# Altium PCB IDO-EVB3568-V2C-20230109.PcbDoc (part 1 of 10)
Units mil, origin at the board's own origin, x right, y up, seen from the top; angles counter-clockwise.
Board outline 5318 x 3544 mil, 2 copper layers (TOP, BOTTOM), stack 6.8 mil thick; 790 components, 626 nets, 2890 pads, 1922 vias.
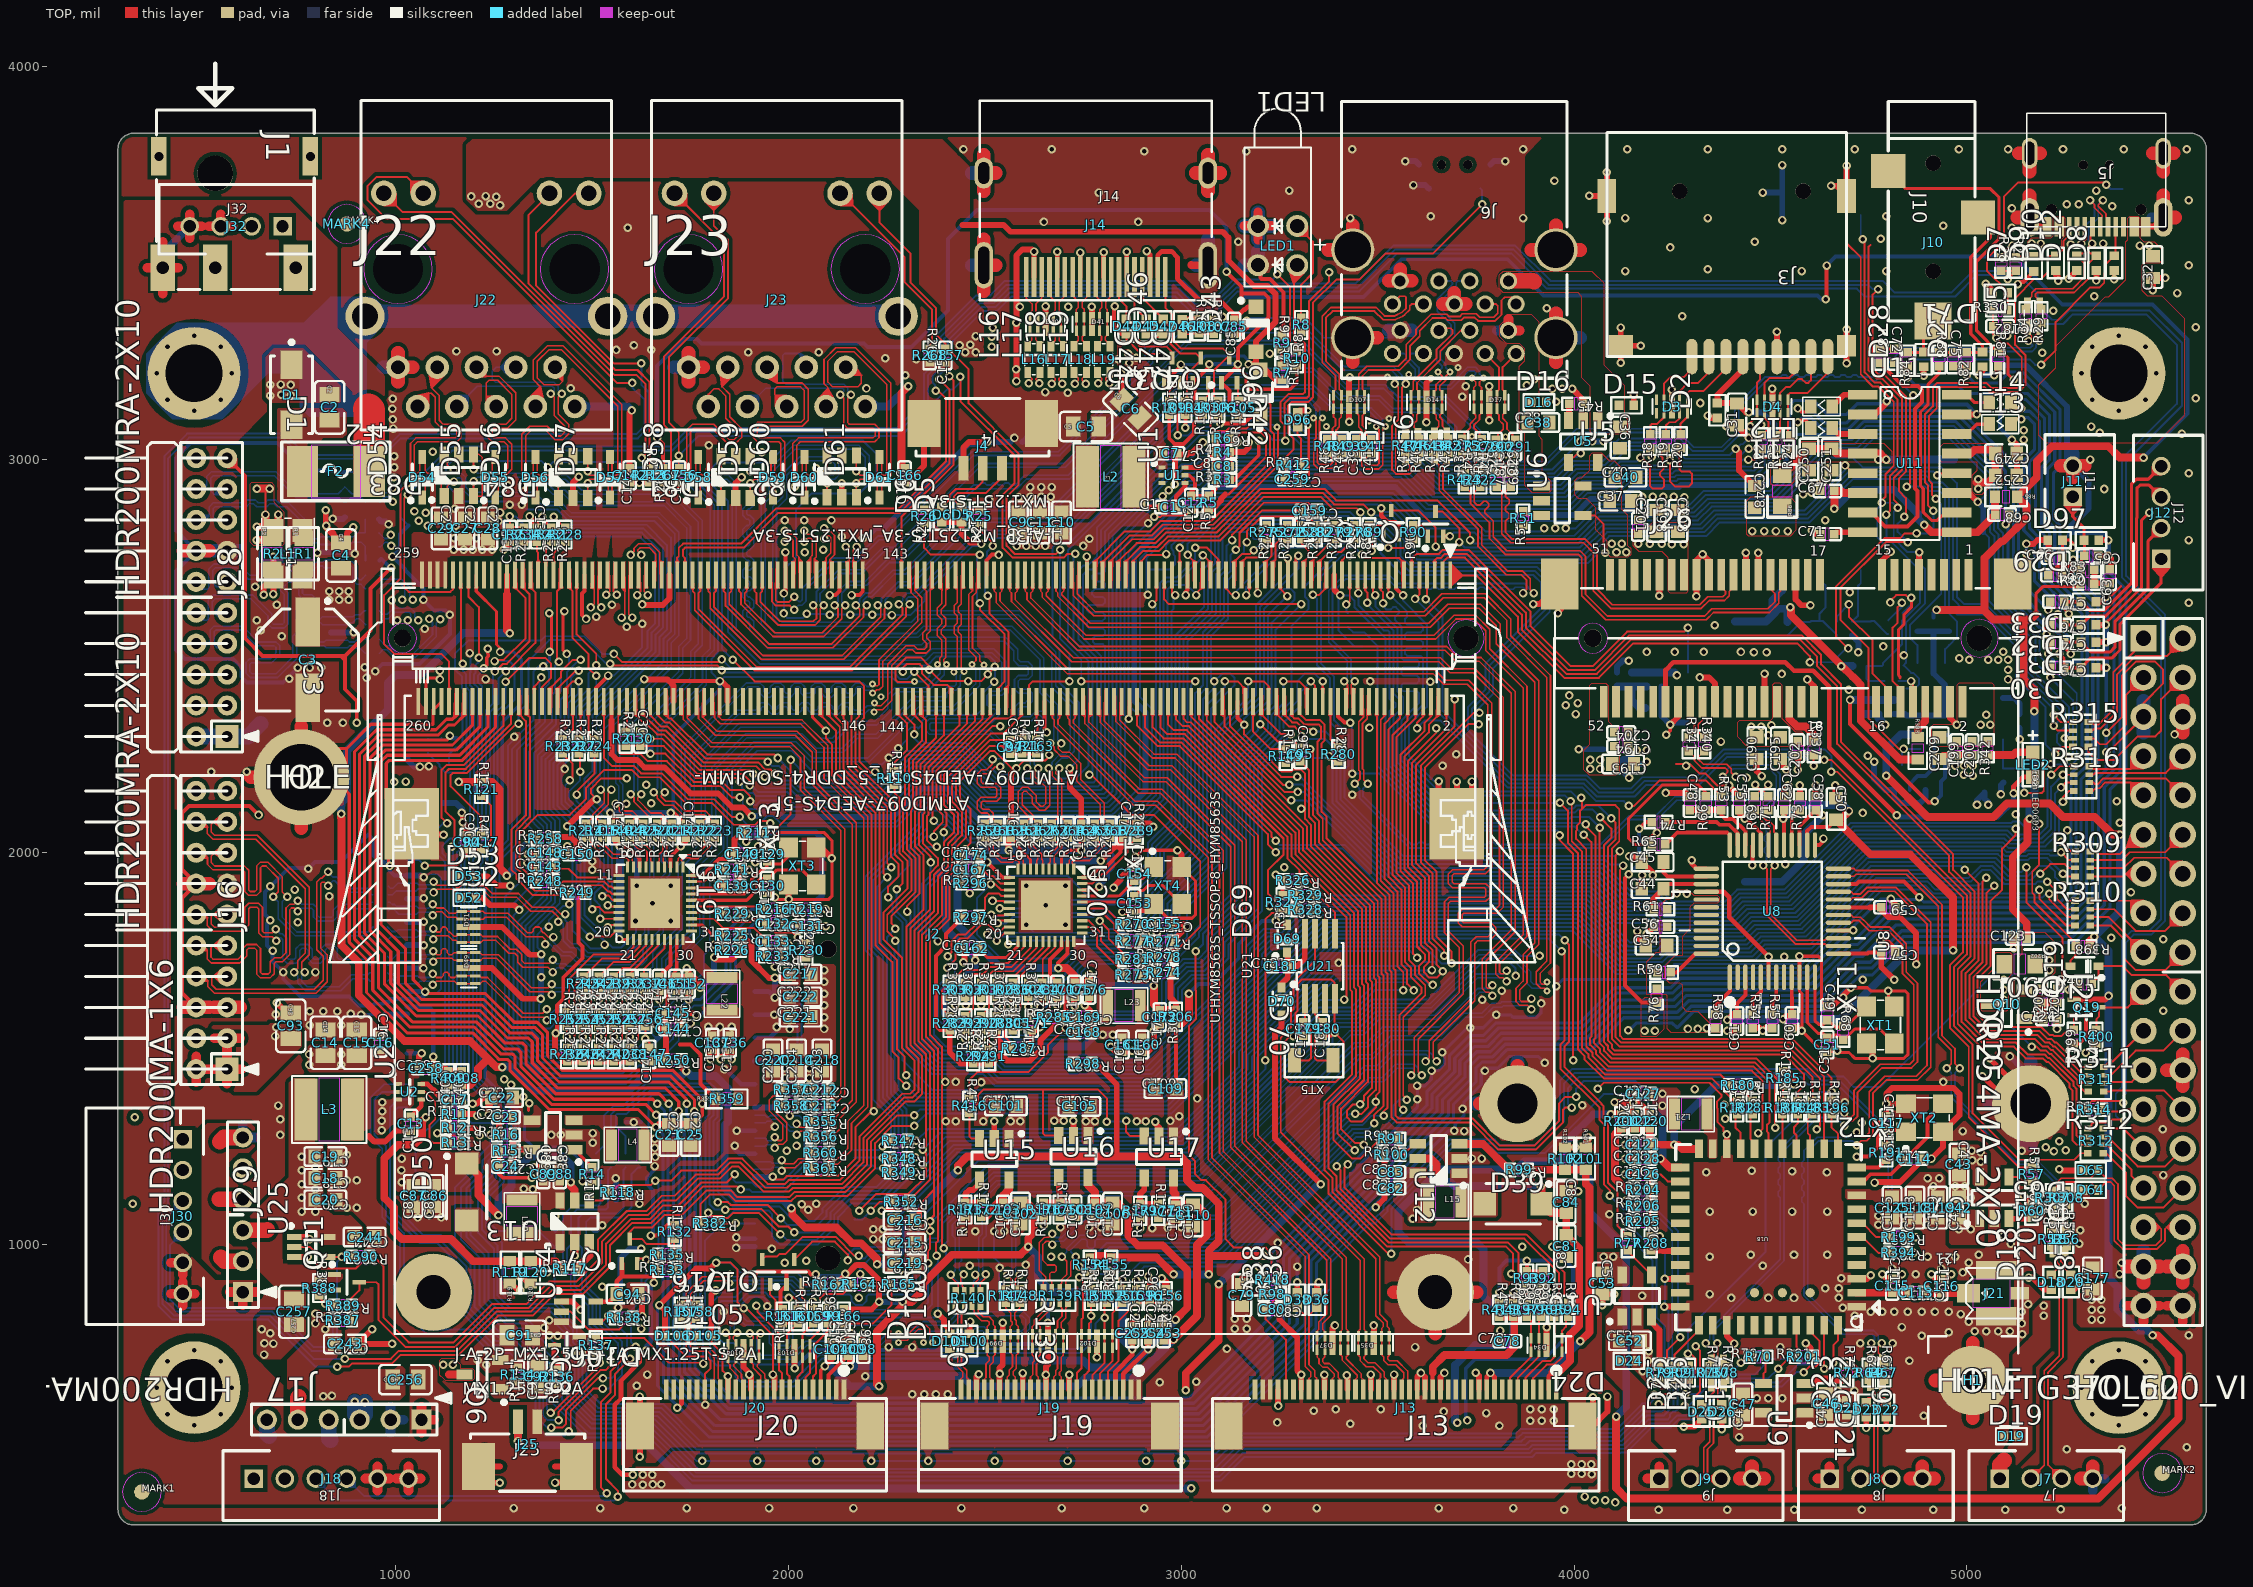
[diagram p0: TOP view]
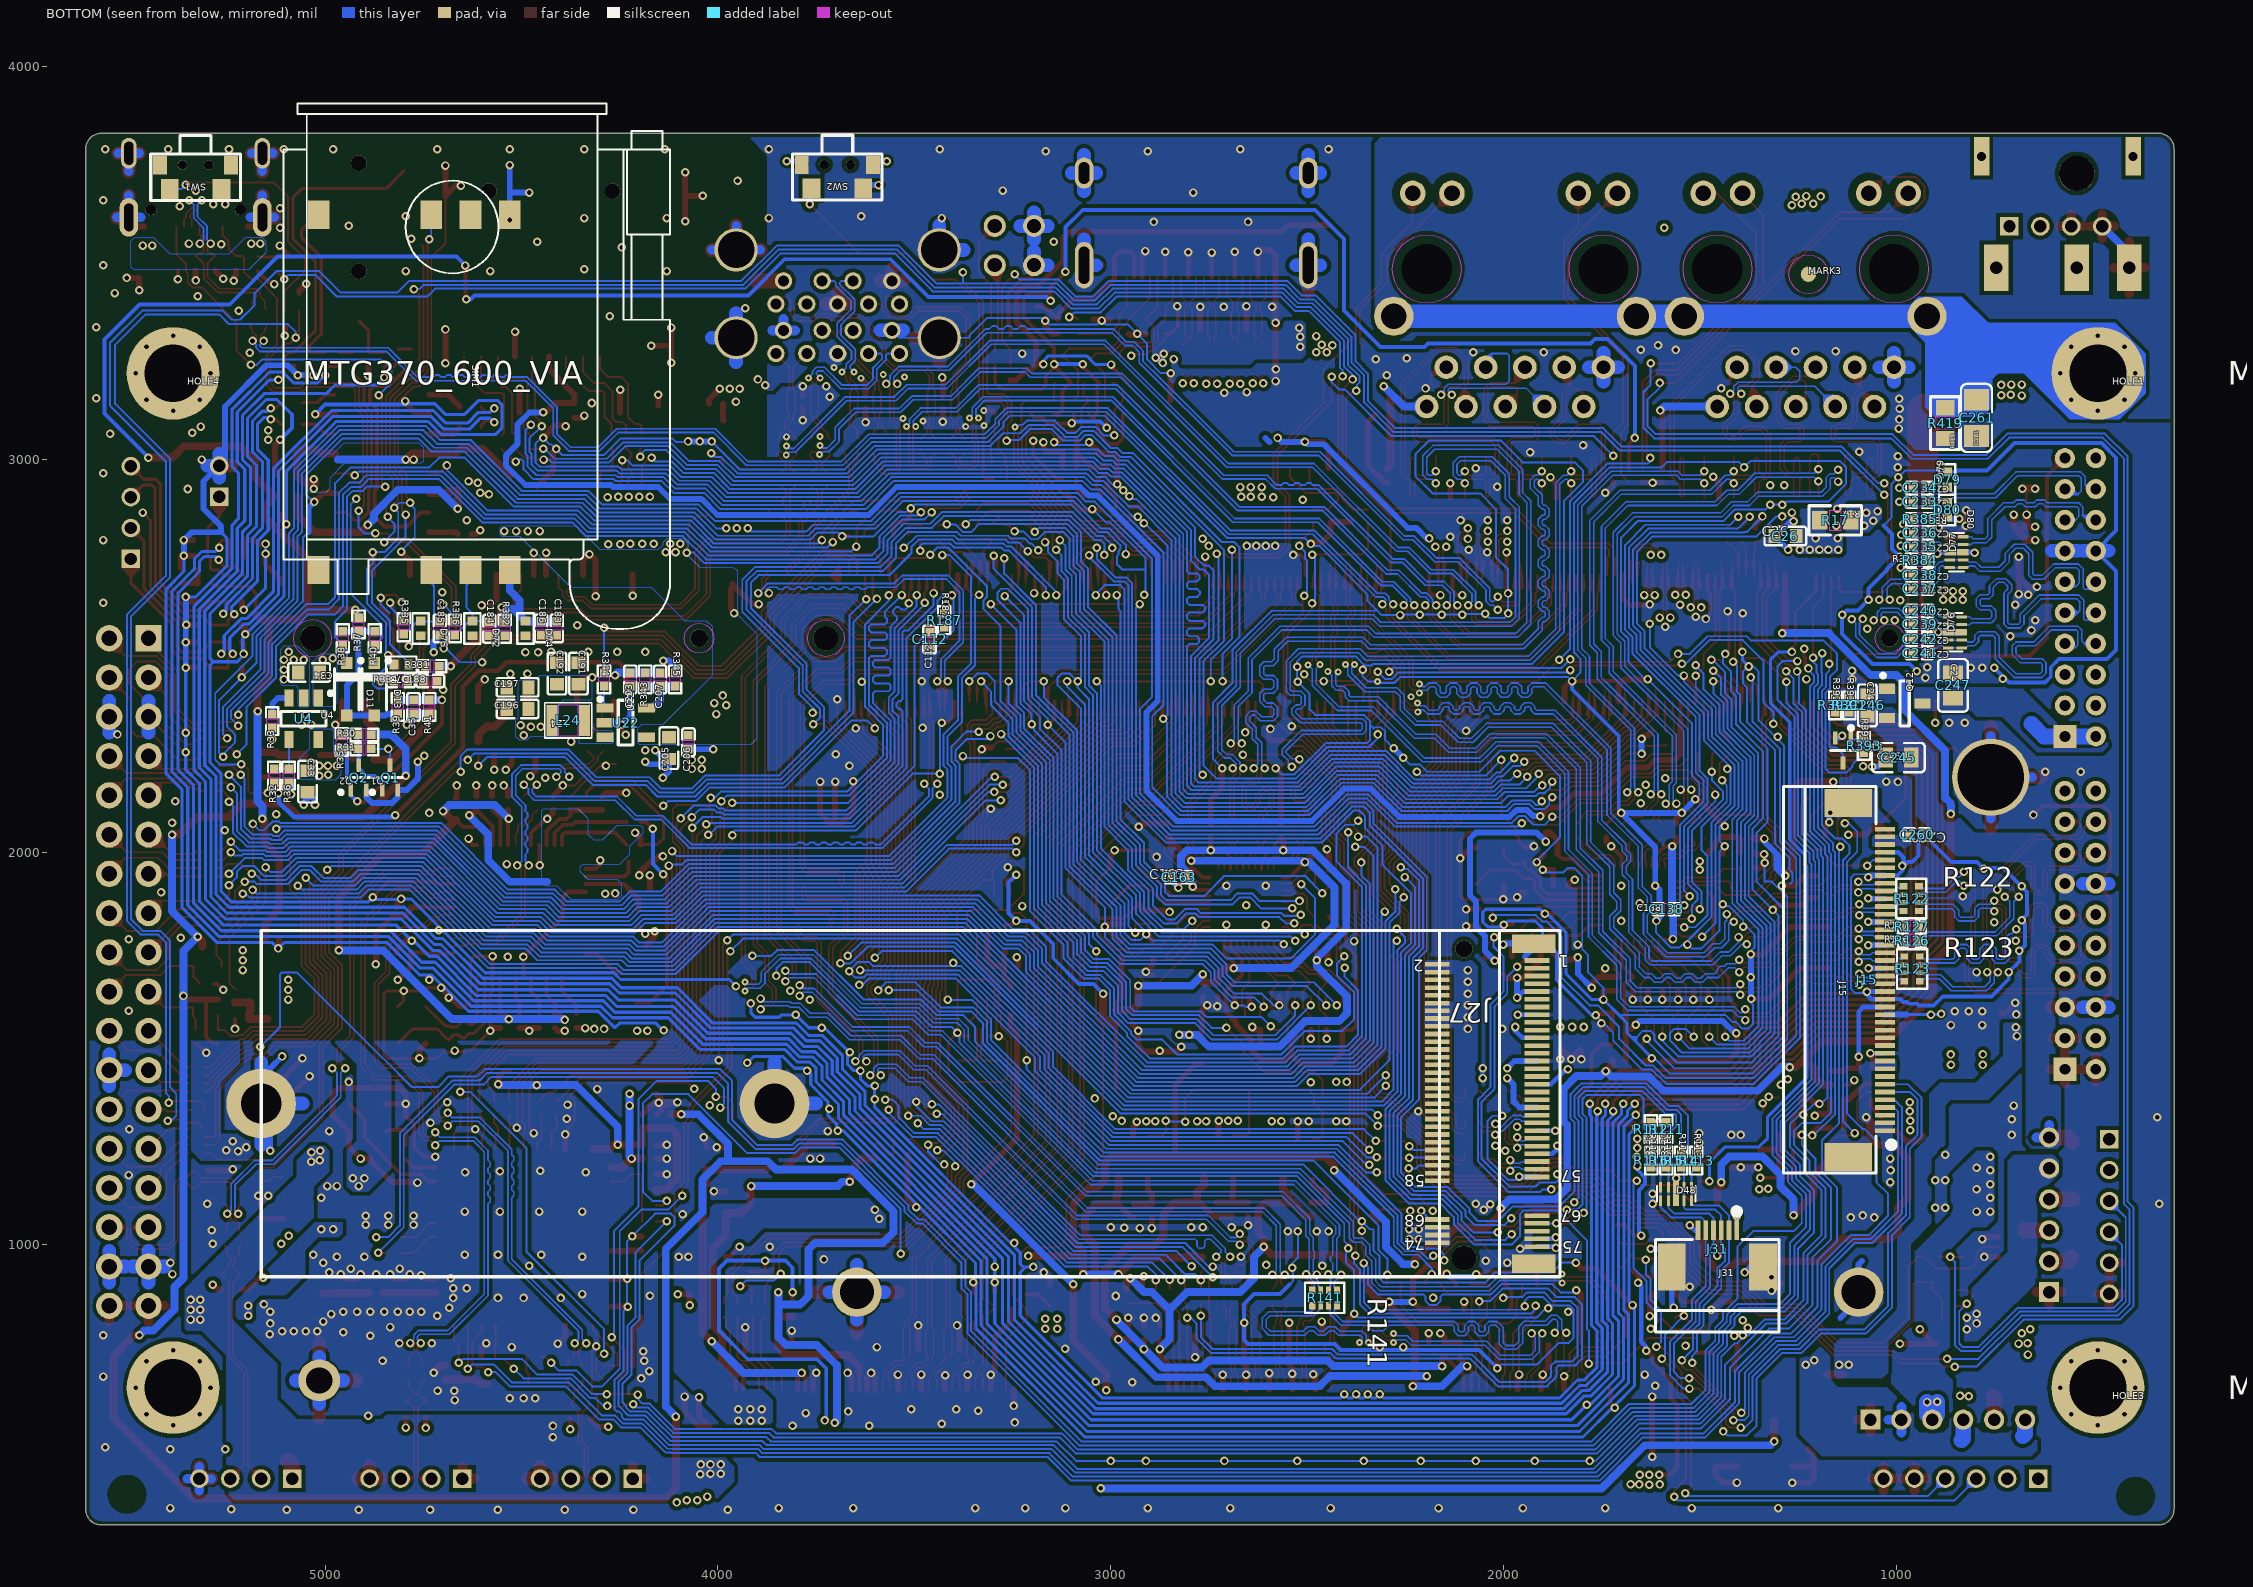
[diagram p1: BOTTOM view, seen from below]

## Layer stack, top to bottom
Top Solder: solder mask 0.4, Solder Resist, Dk 3.5
TOP: signal copper 1.65
Dielectric 1: core 3.5, FR-4, Dk 4.5
BOTTOM: signal copper 1.65
Bottom Solder: solder mask 0.4, Solder Resist, Dk 3.5

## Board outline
4436,3831 5570,3831 cw(c5570,3791) 5610,327 cw(c5570,327) 332,287 cw(c332,327) 292,3791 cw(c332,3791) 4309,3831

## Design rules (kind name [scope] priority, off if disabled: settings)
Clearance [All] p1: gap=10 ignorepadtopadclearanceinfootprint=FALSE except(0: Arc-Hole Track-Hole SMDPad-Hole THPad-Hole Via-Hole Fill-Hole Poly-Hole Region-Hole Text-Hole)
DiffPairsRouting [All] p1: maxlimit=10 minlimit=10 mostfreqgap=10 toplayer_minwidth=15 toplayer_maxwidth=15 toplayer_prefwidth=15 bottomlayer_minwidth=15 bottomlayer_maxwidth=15 bottomlayer_prefwidth=15 maxuncoupledlength=500
PlaneConnect [All] p1: planeconnectstyle=Direct reliefexpansion=20 reliefentries=4 reliefconductorwidth=10 reliefairgap=10
PolygonConnect [All] p1: connectstyle=Direct reliefconductorwidth=10 reliefentries=4 polygonreliefangle="90 Angle" airgapwidth=10
RoutingVias [All] p1: holewidth=28 width=50 viastyle="Through Hole" minholewidth=28 minwidth=50 maxholewidth=28 maxwidth=50
SolderMaskExpansion [All] p1: expansion=4 istentingtop=FALSE
Width [All] p1: maxlimit=10 minlimit=10 preferedwidth=10 impedanceprofiledriven=TRUE minimp=186.350000 maximp=187.750000 favimp=169.560000
28 further rules are at their usual default settings.

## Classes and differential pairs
differential pair DP2: +USB3_OTG0_SSTXN_ -USB3_OTG0_SSTXP_
differential pair DIFFPAIR52: +USB3_OTG0_SSTXN -USB3_OTG0_SSTXP
differential pair DP1: +USB3_OTG0_SSRXN_ -USB3_OTG0_SSRXP_
differential pair DIFFPAIR51: +USB3_OTG0_SSRXN -USB3_OTG0_SSRXP
differential pair DIFFPAIR91: +USB3_OTG0_DM_ -USB3_OTG0_DP_
differential pair DIFFPAIR50: +USB3_OTG0_DM -USB3_OTG0_DP
differential pair DIFFPAIR14: +USB3_HOST1_SSTXN_ -USB3_HOST1_SSTXP_
differential pair DIFFPAIR21: +USB3_HOST1_SSTXN -USB3_HOST1_SSTXP
differential pair DIFFPAIR15: +USB3_HOST1_SSRXN_ -USB3_HOST1_SSRXP_
differential pair DIFFPAIR20: +USB3_HOST1_SSRXN -USB3_HOST1_SSRXP
differential pair DIFFPAIR16: +USB3_HOST1_DM_ -USB3_HOST1_DP_
differential pair DIFFPAIR19: +USB3_HOST1_DM -USB3_HOST1_DP
differential pair DIFFPAIR49: +USB2_HOST3_DM -USB2_HOST3_DP
differential pair DIFFPAIR17: +USB2_HOST2_DM_ -USB2_HOST2_DP_
differential pair DIFFPAIR18: +USB2_HOST2_DM -USB2_HOST2_DP
differential pair DIFFPAIR79: +PHY1_MDI3- -PHY1_MDI3+
differential pair DIFFPAIR82: +PHY1_MDI2- -PHY1_MDI2+
differential pair DIFFPAIR80: +PHY1_MDI1- -PHY1_MDI1+
differential pair DIFFPAIR81: +PHY1_MDI0- -PHY1_MDI0+
differential pair DIFFPAIR83: +PHY0_MDI3- -PHY0_MDI3+
differential pair DIFFPAIR84: +PHY0_MDI2- -PHY0_MDI2+
differential pair DIFFPAIR85: +PHY0_MDI1- -PHY0_MDI1+
differential pair DIFFPAIR86: +PHY0_MDI0- -PHY0_MDI0+
differential pair DIFFPAIR60: +PCIE20_TXN_ -PCIE20_TXP_
differential pair DIFFPAIR37: +PCIE20_TXN -PCIE20_TXP
differential pair DIFFPAIR62: +PCIE20_TX_N -PCIE20_TX_P
differential pair DIFFPAIR59: +PCIE20_RXN_ -PCIE20_RXP_
differential pair DIFFPAIR36: +PCIE20_RXN -PCIE20_RXP
differential pair DIFFPAIR61: +PCIE20_REFCLKN_ -PCIE20_REFCLKP_
differential pair DIFFPAIR35: +PCIE20_REFCLKN -PCIE20_REFCLKP
differential pair DIFFPAIR22: +MIPI_DSI_TX1_D3N -MIPI_DSI_TX1_D3P
differential pair DIFFPAIR23: +MIPI_DSI_TX1_D2N -MIPI_DSI_TX1_D2P
differential pair DIFFPAIR25: +MIPI_DSI_TX1_D1N -MIPI_DSI_TX1_D1P
differential pair DIFFPAIR78: +MIPI_DSI_TX1_D0N -MIPI_DSI_TX1_D0P
differential pair DIFFPAIR24: +MIPI_DSI_TX1_CLKN -MIPI_DSI_TX1_CLKP
differential pair DIFFPAIR26: +MIPI_DSI_TX0_D3N -MIPI_DSI_TX0_D3P
differential pair DIFFPAIR27: +MIPI_DSI_TX0_D2N -MIPI_DSI_TX0_D2P
differential pair DIFFPAIR29: +MIPI_DSI_TX0_D1N -MIPI_DSI_TX0_D1P
differential pair DIFFPAIR64: +MIPI_DSI_TX0_D0N -MIPI_DSI_TX0_D0P
differential pair DIFFPAIR28: +MIPI_DSI_TX0_CLKN -MIPI_DSI_TX0_CLKP
differential pair DIFFPAIR45: +MIPI_CSI_RX_D3N -MIPI_CSI_RX_D3P
differential pair DIFFPAIR46: +MIPI_CSI_RX_D2N -MIPI_CSI_RX_D2P
differential pair DIFFPAIR47: +MIPI_CSI_RX_D1N -MIPI_CSI_RX_D1P
differential pair DIFFPAIR48: +MIPI_CSI_RX_D0N -MIPI_CSI_RX_D0P
differential pair DIFFPAIR43: +MIPI_CSI_RX_CLK1N -MIPI_CSI_RX_CLK1P
differential pair DIFFPAIR44: +MIPI_CSI_RX_CLK0N -MIPI_CSI_RX_CLK0P
differential pair DIFFPAIR53: +MIPI_CSI_D3N_ -MIPI_CSI_D3P_
differential pair DIFFPAIR77: +MIPI_CSI_D3N -MIPI_CSI_D3P
differential pair DIFFPAIR54: +MIPI_CSI_D2N_ -MIPI_CSI_D2P_
differential pair DIFFPAIR55: +MIPI_CSI_D2N -MIPI_CSI_D2P
differential pair DIFFPAIR57: +MIPI_CSI_D1N -MIPI_CSI_D1P
differential pair DIFFPAIR58: +MIPI_CSI_D0N -MIPI_CSI_D0P
differential pair DIFFPAIR87: +MIPI_CSI_CLK1N -MIPI_CSI_CLK1P
differential pair DIFFPAIR56: +MIPI_CSI_CLK0N -MIPI_CSI_CLK0P
differential pair DIFFPAIR68: +LVDS_TX0_D3N -LVDS_TX0_D3P
differential pair DIFFPAIR67: +LVDS_TX0_D2N -LVDS_TX0_D2P
differential pair DIFFPAIR65: +LVDS_TX0_D1N -LVDS_TX0_D1P
differential pair DIFFPAIR63: +LVDS_TX0_D0N -LVDS_TX0_D0P
differential pair DIFFPAIR66: +LVDS_TX0_CLKN -LVDS_TX0_CLKP
differential pair DIFFPAIR73: +LAN1_D- -LAN1_D+
differential pair DIFFPAIR74: +LAN1_C- -LAN1_C+
differential pair DIFFPAIR75: +LAN1_B- -LAN1_B+
differential pair DIFFPAIR76: +LAN1_A- -LAN1_A+
differential pair DIFFPAIR69: +LAN0_D- -LAN0_D+
differential pair DIFFPAIR70: +LAN0_C- -LAN0_C+
differential pair DIFFPAIR71: +LAN0_B- -LAN0_B+
differential pair DIFFPAIR72: +LAN0_A- -LAN0_A+
differential pair DIFFPAIR0: +HDMI_TX_D2N_ -HDMI_TX_D2P_
differential pair DIFFPAIR7: +HDMI_TX_D2N -HDMI_TX_D2P
differential pair DIFFPAIR1: +HDMI_TX_D1N_ -HDMI_TX_D1P_
differential pair DIFFPAIR6: +HDMI_TX_D1N -HDMI_TX_D1P
differential pair DIFFPAIR2: +HDMI_TX_D0N_ -HDMI_TX_D0P_
differential pair DIFFPAIR5: +HDMI_TX_D0N -HDMI_TX_D0P
differential pair DIFFPAIR3: +HDMI_TX_CLKN_ -HDMI_TX_CLKP_
differential pair DIFFPAIR4: +HDMI_TX_CLKN -HDMI_TX_CLKP
differential pair DIFFPAIR92: +FE1_1_DM4 -FE1_1_DP4
differential pair DIFFPAIR11: +FE1_1_DM3 -FE1_1_DP3
differential pair DIFFPAIR8: +FE1_1_DM2 -FE1_1_DP2
differential pair DIFFPAIR13: +FE1_1_DM1 -FE1_1_DP1
differential pair DIFFPAIR94: +FE1_1_DM0 -FE1_1_DP0
differential pair DIFFPAIR34: +EDP_TX_D3N_ -EDP_TX_D3P_
differential pair DIFFPAIR41: +EDP_TX_D3N -EDP_TX_D3P
differential pair DIFFPAIR32: +EDP_TX_D2N_ -EDP_TX_D2P_
differential pair DIFFPAIR40: +EDP_TX_D2N -EDP_TX_D2P
differential pair DIFFPAIR31: +EDP_TX_D1N_ -EDP_TX_D1P_
differential pair DIFFPAIR39: +EDP_TX_D1N -EDP_TX_D1P
differential pair DIFFPAIR30: +EDP_TX_D0N_ -EDP_TX_D0P_
differential pair DIFFPAIR38: +EDP_TX_D0N -EDP_TX_D0P
differential pair DIFFPAIR33: +EDP_TX_AUXN_ -EDP_TX_AUXP_
differential pair DIFFPAIR42: +EDP_TX_AUXN -EDP_TX_AUXP
differential pair DIFFPAIR93: +DM4 -DP4
differential pair DIFFPAIR10: +DM3_ -DP3_
differential pair DIFFPAIR9: +DM2_ -DP2_
differential pair DIFFPAIR12: +DM1_ -DP1_
differential pair DIFFPAIR88: +DM_1 -DP_1
differential pair DIFFPAIR89: +5G_SSTXN -5G_SSTXP
differential pair DIFFPAIR90: +5G_SSRXN -5G_SSRXP

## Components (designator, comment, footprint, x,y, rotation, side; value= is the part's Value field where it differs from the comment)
C1 "C-0402_C0402_100NF" SILKSCREEN_TOP#1 2969,2878.99 r0 top
C2 "C-0805_C0805_10UF" SILKSCREEN_TOP#2 831,3133 r270 top
C3 "C-AL-SMD_CAPAE660X770_100UF/25V" SILKSCREEN_TOP#3 775,2490 r270 top
C4 "C-0805_C0805_10UF" SILKSCREEN_TOP#2 860,2756 r270 top
C5 "C-0805_C0805_10UF" SILKSCREEN_TOP#2 2757,3084 r0 top
C6 "C-0805_C0805_10UF" SILKSCREEN_TOP#2 2870.72,3129.11 r315 top
C7 "C-0402_C0402_100NF" SILKSCREEN_TOP#1 2972,3016.01 r180 top
C8 "C-0402_C0402_100PF" SILKSCREEN_TOP#1 3105,2982.99 r0 top
C9 "C-0805_C0603_22UF" SILKSCREEN_TOP#4 2585,2840 r90 top
C10 "C-0805_C0603_22UF" SILKSCREEN_TOP#4 2695,2840 r90 top
C11 "C-0805_C0603_22UF" SILKSCREEN_TOP#4 2640,2840 r90 top
C12 "C-0402_C0402_100NF" SILKSCREEN_TOP#1 3025.01,2890 r90 top
C13 "C-0402_C0402_100NF" SILKSCREEN_TOP#1 1038.01,1309 r90 top
C14 "C-0805_C0805_10UF" SILKSCREEN_TOP#2 820,1515 r270 top
C15 "C-0805_C0805_10UF" SILKSCREEN_TOP#2 900,1515 r270 top
C16 "C-0402_C0402_100NF" SILKSCREEN_TOP#1 959.99,1515 r270 top
C17 "C-0402_C0402_100PF" SILKSCREEN_TOP#1 1150,1369.99 r0 top
C18 "C-0805_C0603_22UF" SILKSCREEN_TOP#4 820,1170 r180 top
C19 "C-0805_C0603_22UF" SILKSCREEN_TOP#4 820,1225 r180 top
C20 "C-0805_C0603_22UF" SILKSCREEN_TOP#4 820,1115 r180 top
C21 "C-0603_C0603_22UF" SILKSCREEN_TOP#4 1695,1280 r270 top
C22 "C-0603_C0603_10UF" SILKSCREEN_TOP#4 1270,1375 r0 top
C23 "C-0402_C0402_1UF" SILKSCREEN_TOP#1 1280,1324.99 r0 top
C24 "C-0402_C0402_47PF" SILKSCREEN_TOP#1 1280,1200.01 r180 top
C25 "C-0603_C0603_22UF" SILKSCREEN_TOP#4 1750,1280 r270 top
C26 "C-0805_C0603_22UF" SILKSCREEN_BOTTOM#1 1282,2805 r0 bottom
C27 "C-0805_C0603_22UF" SILKSCREEN_TOP#4 1176,2825 r270 top
C28 "C-0805_C0603_22UF" SILKSCREEN_TOP#4 1234,2825 r270 top
C29 "C-0805_C0603_22UF" SILKSCREEN_TOP#4 1115,2825 r270 top
C30 "C-0402_C0402_6.8PF" SILKSCREEN_TOP#1 1621.99,2289 r270 top
C31 "C-0603_C0603_10UF" ASSEMBLY_TOP#1 4415,3115 r90 top
C32 "C-0603_C0603_10UF" ASSEMBLY_TOP#1 5474,3490 r90 top
C33 "C-0603_C0603_10UF" ASSEMBLY_BOTTOM#1 5045,2180 r270 bottom
C34 "C-0603_C0603_10UF" ASSEMBLY_BOTTOM#1 5041,2458 r0 bottom
C35 "C-0402_C0402_1UF" ASSEMBLY_BOTTOM#2 4774.99,2370 r90 bottom
C36 "C-0603_C0603_10UF" ASSEMBLY_TOP#1 4117,3056 r270 top
C37 "C-0603_C0603_10UF" ASSEMBLY_TOP#1 4118,2894 r0 top
C38 "C-0603_C0603_10UF" SILKSCREEN_TOP#4 3909,3094 r0 top
C39 "C-0402_C0402_100NF" SILKSCREEN_TOP#1 3445.01,3034 r90 top
C40 "C-0603_C0603_10UF" SILKSCREEN_TOP#4 4131,2955 r0 top
C41 "C-0402_C0402_100NF" SILKSCREEN_TOP#1 3483.01,3034 r90 top
C42 "C-0603_C0603_10UF" SILKSCREEN_TOP#4 4980,1095 r90 top
C43 "C-0603_C0603_10UF" SILKSCREEN_TOP#4 4980,1205 r270 top
C44 "C-0603_C0603_10UF" ASSEMBLY_TOP#1 4200,1907 r0 top
C45 "C-0603_C0603_10UF" ASSEMBLY_TOP#1 4200,1975 r0 top
C46 "C-0603_C0603_10UF" SILKSCREEN_TOP#4 4642,595 r90 top
C47 "C-0603_C0603_10UF" SILKSCREEN_TOP#4 4430,594 r90 top
C48 "C-0402_C0402_NC/1UF" ASSEMBLY_TOP#2 4294.99,2125 r270 top
C49 "C-0402_C0402_18PF" ASSEMBLY_TOP#2 4644.99,1590 r270 top
C50 "C-0603_C0603_10UF" ASSEMBLY_TOP#1 4667,2110 r270 top
C51 "C-0402_C0402_18PF" SILKSCREEN_TOP#1 4645.01,1510 r90 top
C52 "C-0603_C0603_10UF" SILKSCREEN_TOP#4 4142,756 r0 top
C53 "C-0603_C0603_10UF" SILKSCREEN_TOP#4 4072,902 r270 top
C54 "C-0603_C0603_10UF" ASSEMBLY_TOP#1 4210,1763 r0 top
C55 "C-0402_C0402_100NF" ASSEMBLY_TOP#2 4419.99,2125 r270 top
C56 "C-0402_C0402_100NF" ASSEMBLY_TOP#2 4220,1809.99 r0 top
C57 "C-0402_C0402_100NF" ASSEMBLY_TOP#2 4800,1745.01 r180 top
C58 "C-0402_C0402_100NF" ASSEMBLY_TOP#2 4614.99,2125 r270 top
C59 "C-0402_C0402_100NF" ASSEMBLY_TOP#2 4800,1860.01 r180 top
C60 "C-0402_C0402_100NF" ASSEMBLY_TOP#2 4555.01,1570 r90 top
C61 "C-0402_C0402_100NF" ASSEMBLY_TOP#2 4415.01,1570 r90 top
C62 "C-0402_C0402_100NF" ASSEMBLY_TOP#2 4534.99,2125 r270 top
C63 "C-0402_C0402_1UF" ASSEMBLY_TOP#2 5364.01,2703 r90 top
C64 "C-0402_C0402_1UF" ASSEMBLY_TOP#2 5225,2705.01 r180 top
C65 "C-0402_C0402_220PF" ASSEMBLY_TOP#2 5317,2755.01 r180 top
C66 "C-0402_C0402_1UF" ASSEMBLY_TOP#2 5226,2749.99 r0 top
C67 "C-0402_C0402_100NF" ASSEMBLY_TOP#2 4645,2919.99 r0 top
C68 "C-0402_C0402_100NF" ASSEMBLY_TOP#2 5090,2860.01 r180 top
C71 "C-0402_C0402_1UF" ASSEMBLY_TOP#2 4645,2809.99 r0 top
C72 "C-0402_C0402_100NF" ASSEMBLY_TOP#2 4814.99,3264 r270 top
C73 "C-0402_C0402_1NF" ASSEMBLY_TOP#2 5230,2470.01 r180 top
C74 "C-0402_C0402_1NF" ASSEMBLY_TOP#2 5230,2535.01 r180 top
C75 "C-0402_C0402_100NF" ASSEMBLY_TOP#2 4964.99,3255 r270 top
C76 "C-0402_C0402_1NF" ASSEMBLY_TOP#2 5230,2579.01 r180 top
C77 "C-0402_C0402_1NF" ASSEMBLY_TOP#2 5230,2638.01 r180 top
C78 "C-0402_C0402_1UF" SILKSCREEN_TOP#1 3830,754.99 r0 top
C79 "C-0603_C0603_10UF" SILKSCREEN_TOP#4 3154,872 r270 top
C80 "C-0402_C0402_NC/1UF" SILKSCREEN_TOP#1 3232,836.01 r180 top
C81 "C-0603_C0603_1UF" SILKSCREEN_TOP#4 3980,997 r90 top
C82 "C-0402_C0402_100NF" SILKSCREEN_TOP#1 3535,1144.99 r0 top
C83 "C-0402_C0402_4.7UF" SILKSCREEN_TOP#1 3535,1184.99 r0 top
C84 "C-0603_C0603_1UF" SILKSCREEN_TOP#4 3980,1109 r270 top
C85 "C-0402_C0402_100NF" SILKSCREEN_TOP#1 3134.01,3338 r90 top
C86 "C-0603_C0603_1UF" SILKSCREEN_TOP#4 1097,1125 r90 top
C87 "C-0603_C0603_1UF" SILKSCREEN_TOP#4 1044,1125 r90 top
C88 "C-0402_C0402_100NF" SILKSCREEN_TOP#1 1416.99,1180 r270 top
C89 "C-0402_C0402_4.7UF" SILKSCREEN_TOP#1 1374.99,1180 r270 top
C90 "C-0402_C0402_NC/1UF" SILKSCREEN_TOP#1 1179.99,2025 r270 top
C91 "C-0805_C0805_10UF" SILKSCREEN_TOP#2 1315,770 r180 top
C92 "C-0603_C0603_1UF" SILKSCREEN_TOP#4 1360,665 r90 top
C93 "C-0805_C0805_10UF" SILKSCREEN_TOP#2 732,1558 r270 top
C94 "C-0603_C0603_NC/1UF" SILKSCREEN_TOP#4 1590,875 r180 top
C95 "C-0402_C0402_NC/6.8PF" SILKSCREEN_TOP#1 3302.99,2249 r270 top
C96 "C-0402_C0402_100NF" SILKSCREEN_TOP#1 2919.99,870 r270 top
C97 "C-0402_C0402_NC/6.8PF" SILKSCREEN_TOP#1 2563.99,2268 r270 top
C98 "C-0402_C0402_100NF" SILKSCREEN_TOP#1 2189.99,735 r270 top
C99 "C-0402_C0402_100NF" SILKSCREEN_TOP#1 2099.99,818 r270 top
C100 "C-0402_C0402_100NF" SILKSCREEN_TOP#1 2149.99,735 r270 top
C101 "C-0603_C0603_10UF" SILKSCREEN_TOP#4 2553,1354 r0 top
C102 "C-0603_C0603_10UF" SILKSCREEN_TOP#4 2590,1080 r90 top
C103 "C-0402_C0402_100NF" SILKSCREEN_TOP#1 2546.01,1090 r90 top
C104 "C-0402_C0402_100NF" SILKSCREEN_TOP#1 2109.99,735 r270 top
C105 "C-0603_C0603_10UF" SILKSCREEN_TOP#4 2740,1353 r0 top
C106 "C-0603_C0603_10UF" SILKSCREEN_TOP#4 2825,1080 r90 top
C107 "C-0402_C0402_100NF" SILKSCREEN_TOP#1 2780.01,1090 r90 top
C108 "C-0402_C0402_NC/18PF" SILKSCREEN_TOP#1 2730.01,1090 r90 top
C109 "C-0603_C0603_10UF" SILKSCREEN_TOP#4 2959,1398 r0 top
C110 "C-0603_C0603_10UF" SILKSCREEN_TOP#4 3030,1075 r90 top
C111 "C-0402_C0402_100NF" SILKSCREEN_TOP#1 2985.01,1085 r90 top
C112 "C-0402_C0402_NC/6.8PF" SILKSCREEN_BOTTOM#2 3460.99,2542 r90 bottom
C113 "C-0402_C0402_10PF" SILKSCREEN_TOP#1 4870,878.01 r180 top
C114 "C-0402_C0402_NC/18PF" SILKSCREEN_TOP#1 4865,1219.99 r0 top
C115 "C-0402_C0402_NC/10PF" SILKSCREEN_TOP#1 4809.99,896 r270 top
C116 "C-0402_C0402_NC/10PF" SILKSCREEN_TOP#1 4934.99,895 r270 top
C117 "C-0402_C0402_NC/18PF" SILKSCREEN_TOP#1 4794.99,1310 r270 top
C118 "C-0603_C0603_22UF" SILKSCREEN_TOP#4 4868,1095 r90 top
C119 "C-0603_C0603_22UF" SILKSCREEN_TOP#4 4926,1095 r90 top
C120 "C-0402_C0402_1UF" SILKSCREEN_TOP#1 4192.99,1315 r270 top
C121 "C-0402_C0402_1UF" SILKSCREEN_TOP#1 4175,1254.99 r0 top
C122 "C-0402_C0402_100NF" SILKSCREEN_TOP#1 4154.99,1315 r270 top
C123 "C-0402_C0402_100NF" ASSEMBLY_TOP#2 5135,1779.99 r0 top
C124 "C-0402_C0402_1UF" ASSEMBLY_TOP#2 5212,1574.99 r0 top
C125 "C-0603_C0603_10UF" SILKSCREEN_TOP#4 4810,1095 r90 top
C126 "C-0402_C0402_NC/6.8PF" SILKSCREEN_TOP#1 4175,1179.99 r0 top
C127 "C-0402_C0402_4.7UF" SILKSCREEN_TOP#1 4175,1384.99 r0 top
C128 "C-0402_C0402_100NF" SILKSCREEN_TOP#1 4175,1219.99 r0 top
C129 "C-0402_C0402_18PF" SILKSCREEN_TOP#1 1944.99,1995 r270 top
C130 "C-0402_C0402_18PF" SILKSCREEN_TOP#1 1945.01,1915 r90 top
C131 "C-0402_C0402_NC/6.8PF" SILKSCREEN_TOP#1 2045,1812.01 r180 top
C132 "C-0402_C0402_NC/100PF" SILKSCREEN_TOP#1 1960,1818.01 r180 top
C133 "C-0402_C0402_NC/100PF" SILKSCREEN_TOP#1 1960,1772.01 r180 top
C134 "C-0402_C0402_NC/6.8PF" SILKSCREEN_TOP#1 1358.99,2809 r270 top
C135 "C-0402_C0402_NC/6.8PF" SILKSCREEN_TOP#1 1290.01,2809 r90 top
C136 "C-0402_C0402_4.7UF" SILKSCREEN_TOP#1 1850.01,1515 r90 top
C137 "C-0402_C0402_100NF" SILKSCREEN_TOP#1 1805.01,1515 r90 top
C138 "C-0402_C0402_100NF" SILKSCREEN_BOTTOM#3 1585,1854.99 r0 bottom
C139 "C-0402_C0402_100NF" SILKSCREEN_TOP#1 1855,1915.01 r180 top
C140 "C-0402_C0402_100NF" SILKSCREEN_TOP#1 1559.99,2055 r270 top
C141 "C-0402_C0402_100NF" SILKSCREEN_TOP#1 1737.99,2055 r270 top
C142 "C-0402_C0402_10NF" SILKSCREEN_TOP#1 1595.01,2960 r90 top
C143 "C-0402_C0402_100NF" SILKSCREEN_TOP#1 1379,1962.99 r0 top
C144 "C-0402_C0402_1UF" SILKSCREEN_TOP#1 1705,1550.01 r180 top
C145 "C-0402_C0402_1UF" SILKSCREEN_TOP#1 1705,1590.01 r180 top
C146 "C-0402_C0402_100NF" SILKSCREEN_TOP#1 1670.01,1665 r90 top
C147 "C-0402_C0402_NC/6.8PF" SILKSCREEN_TOP#1 1645.01,1485 r90 top
C148 "C-0402_C0402_4.7UF" SILKSCREEN_TOP#1 1379,1998.99 r0 top
C149 "C-0402_C0402_100NF" SILKSCREEN_TOP#1 1880,1995.01 r180 top
C150 "C-0402_C0402_100NF" SILKSCREEN_TOP#1 1460,1994.99 r0 top
C151 "C-0402_C0402_4.7UF" SILKSCREEN_TOP#1 1712.01,1665 r90 top
C152 "C-0402_C0402_100NF" SILKSCREEN_TOP#1 1745.01,1665 r90 top
C153 "C-0402_C0402_18PF" SILKSCREEN_TOP#1 2880.01,1870 r90 top
C154 "C-0402_C0402_18PF" SILKSCREEN_TOP#1 2879.99,1945 r270 top
C155 "C-0402_C0402_NC/6.8PF" SILKSCREEN_TOP#1 2955,1817.01 r180 top
C156 "C-0402_C0402_NC/100PF" SILKSCREEN_TOP#1 1721.01,2960 r90 top
C157 "C-0402_C0402_NC/100PF" SILKSCREEN_TOP#1 2399.01,3265 r90 top
C158 "C-0402_C0402_NC/6.8PF" SILKSCREEN_TOP#1 3304.99,2815 r270 top
C159 "C-0402_C0402_NC/6.8PF" SILKSCREEN_TOP#1 3325,2870.01 r180 top
C160 "C-0402_C0402_4.7UF" SILKSCREEN_TOP#1 2900.01,1510 r90 top
C161 "C-0402_C0402_100NF" SILKSCREEN_TOP#1 2850.01,1510 r90 top
C162 "C-0402_C0402_100NF" SILKSCREEN_TOP#1 2465,1754.99 r0 top
C163 "C-0402_C0402_100NF" SILKSCREEN_BOTTOM#3 2826,1935.99 r0 bottom
C164 "C-0402_C0402_100NF" SILKSCREEN_TOP#1 2745.01,2055 r90 top
C165 "C-0402_C0402_100NF" SILKSCREEN_TOP#1 2565.99,2055 r270 top
C166 "C-0402_C0402_10NF" SILKSCREEN_TOP#1 2295.01,2960 r90 top
C167 "C-0402_C0402_100NF" SILKSCREEN_TOP#1 2462,1954.99 r0 top
C168 "C-0402_C0402_1UF" SILKSCREEN_TOP#1 2750,1541.99 r0 top
C169 "C-0402_C0402_1UF" SILKSCREEN_TOP#1 2750,1580.01 r180 top
C170 "C-0402_C0402_100NF" SILKSCREEN_TOP#1 2684.01,1650 r90 top
C171 "C-0402_C0402_NC/6.8PF" SILKSCREEN_TOP#1 2619.01,1565 r90 top
C172 "C-0402_C0402_4.7UF" SILKSCREEN_TOP#1 2945.01,1580 r90 top
C173 "C-0402_C0402_100NF" SILKSCREEN_TOP#1 2851.99,2055 r270 top
C174 "C-0402_C0402_100NF" SILKSCREEN_TOP#1 2463,1991.99 r0 top
C175 "C-0402_C0402_4.7UF" SILKSCREEN_TOP#1 2728.01,1650 r90 top
C176 "C-0402_C0402_100NF" SILKSCREEN_TOP#1 2764.99,1650 r270 top
C177 "C-0603_C0603_10UF" SILKSCREEN_TOP#4 5320,915 r90 top
C179 "C-0402_C0402_18PF" SILKSCREEN_TOP#1 3310.01,1550 r90 top
C180 "C-0402_C0402_18PF" SILKSCREEN_TOP#1 3360.01,1550 r90 top
C181 "C-0402_C0402_1UF" SILKSCREEN_TOP#1 3253,1709.99 r0 top
C182 "C-0402_C0402_100NF" ASSEMBLY_TOP#2 5085,3340.01 r180 top
C183 "C-0402_C0402_100NF" ASSEMBLY_BOTTOM#2 4410.01,2570 r270 bottom
C184 "C-0402_C0402_33PF" ASSEMBLY_BOTTOM#2 4582.01,2569 r270 bottom
C185 "C-0402_C0402_33PF" ASSEMBLY_BOTTOM#2 4708.01,2570 r270 bottom
C186 "C-0402_C0402_100NF" ASSEMBLY_BOTTOM#2 4450.01,2570 r270 bottom
C187 "C-0402_C0402_NC/100NF" ASSEMBLY_TOP#2 3802.99,2949 r270 top
C188 "C-0402_C0402_33PF" ASSEMBLY_BOTTOM#3 4732,2435.99 r0 bottom
C189 "C-0402_C0402_NC/100NF" ASSEMBLY_TOP#2 3838.99,2949 r270 top
C190 "C-0603_C0603_22UF" ASSEMBLY_TOP#1 4465,2265 r90 top
C191 "C-0603_C0603_22UF" ASSEMBLY_BOTTOM#1 4355,2455 r270 bottom
C192 "C-0603_C0603_22UF" ASSEMBLY_BOTTOM#1 4410,2455 r270 bottom
C193 "C-0603_C0603_22UF" ASSEMBLY_TOP#1 4125,2225 r180 top
C194 "C-0402_C0402_33PF" ASSEMBLY_TOP#2 4120,2270.01 r180 top
C195 "C-0603_C0603_22UF" ASSEMBLY_TOP#1 4525,2265 r90 top
C196 "C-0603_C0603_22UF" ASSEMBLY_BOTTOM#4 4510,2365 r0 bottom
C197 "C-0603_C0603_22UF" ASSEMBLY_BOTTOM#4 4510,2420 r0 bottom
C198 "C-0603_C0603_22UF" ASSEMBLY_TOP#1 4210,2844 r270 top
C199 "C-0402_C0402_33PF" ASSEMBLY_TOP#2 4975.01,2265 r90 top
C200 "C-0402_C0402_100NF" ASSEMBLY_TOP#2 5014.01,2265 r90 top
C201 "C-0402_C0402_10PF" ASSEMBLY_TOP#2 4162.99,2829 r270 top
C202 "C-0402_C0402_33PF" ASSEMBLY_TOP#2 4570.01,2265 r90 top
C203 "C-0402_C0402_100NF" ASSEMBLY_BOTTOM#2 4222.99,2440 r90 bottom
C204 "C-0402_C0402_10PF" ASSEMBLY_TOP#2 4120,2305.01 r180 top
C205 "C-0603_C0603_10UF" ASSEMBLY_BOTTOM#1 4125,2265 r90 bottom
C206 "C-0402_C0402_1UF" ASSEMBLY_BOTTOM#2 4074.99,2280 r90 bottom
C207 "C-0402_C0402_6.8PF" ASSEMBLY_BOTTOM#2 4146.99,2440 r90 bottom
C208 "C-0603_C0603_22UF" ASSEMBLY_TOP#1 4264.39,2843.84 r270 top
C209 "C-0603_C0603_22UF" ASSEMBLY_TOP#1 4930,2265 r90 top
C212 "C-0402_C0402_100NF" SILKSCREEN_TOP#1 2080,1395.01 r180 top
C213 "C-0402_C0402_100NF" SILKSCREEN_TOP#1 2080,1355.01 r180 top
C214 "C-0603_C0603_22UF" SILKSCREEN_TOP#4 2020,1470 r90 top
C215 "C-0603_C0603_22UF" SILKSCREEN_TOP#4 2295,1005 r180 top
C216 "C-0603_C0603_22UF" SILKSCREEN_TOP#4 2295,1063 r180 top
C217 "C-0603_C0603_22UF" SILKSCREEN_TOP#4 2030,1690 r0 top
C218 "C-0603_C0603_22UF" SILKSCREEN_TOP#4 2085,1470 r90 top
C219 "C-0603_C0603_22UF" SILKSCREEN_TOP#4 2295,953 r180 top
C220 "C-0603_C0603_22UF" SILKSCREEN_TOP#4 1960,1470 r90 top
C221 "C-0603_C0603_22UF" SILKSCREEN_TOP#4 2030,1580 r0 top
C222 "C-0603_C0603_22UF" SILKSCREEN_TOP#4 2030,1632 r0 top
C233 "C-0402_C0402_100NF" SILKSCREEN_BOTTOM#2 940,2893.01 r0 bottom
C234 "C-0402_C0402_100NF" SILKSCREEN_BOTTOM#2 940,2928.01 r0 bottom
C235 "C-0402_C0402_100NF" SILKSCREEN_BOTTOM#2 939,2778.01 r0 bottom
C236 "C-0402_C0402_100NF" SILKSCREEN_BOTTOM#2 939,2814.01 r0 bottom
C237 "C-0402_C0402_100NF" SILKSCREEN_BOTTOM#2 940,2671.01 r0 bottom
C238 "C-0402_C0402_100NF" SILKSCREEN_BOTTOM#2 940,2705.01 r0 bottom
C239 "C-0402_C0402_100NF" SILKSCREEN_BOTTOM#2 940,2580.01 r0 bottom
C240 "C-0402_C0402_100NF" SILKSCREEN_BOTTOM#2 940,2615.01 r0 bottom
C241 "C-0402_C0402_100NF" SILKSCREEN_BOTTOM#2 940,2507.01 r0 bottom
C242 "C-0402_C0402_100NF" SILKSCREEN_BOTTOM#2 940,2542.01 r0 bottom
C243 "C-0603_C0603_10UF" SILKSCREEN_TOP#4 870,748 r180 top
C244 "C-0603_C0603_NC/1UF" SILKSCREEN_TOP#4 920,1020 r180 top
C245 "C-0805_C0805_10UF" SILKSCREEN_BOTTOM#4 994,2241 r0 bottom
C246 "C-0603_C0603_1UF" SILKSCREEN_BOTTOM#5 1073,2374 r270 bottom
C247 "C-0805_C0805_10UF" SILKSCREEN_BOTTOM#6 855,2425 r270 bottom
C248 "C-0805_C0603_22UF" ASSEMBLY_TOP#1 4460,2905 r270 top
C249 "C-0805_C0603_22UF" ASSEMBLY_TOP#1 5100,3015 r180 top
C250 "C-0805_C0603_22UF" ASSEMBLY_TOP#1 4598,3000 r90 top
C251 "C-0805_C0603_22UF" ASSEMBLY_TOP#1 4655,3000 r90 top
C252 "C-0805_C0603_22UF" ASSEMBLY_TOP#1 5100,2960 r180 top
C253 "C-0402_C0402_1UF" SILKSCREEN_TOP#1 2954.99,775 r270 top
C254 "C-0402_C0402_1UF" SILKSCREEN_TOP#1 2914.99,775 r270 top
C255 "C-0402_C0402_1UF" SILKSCREEN_TOP#1 2874.99,775 r270 top
C256 "C-0805_C0805_10UF" SILKSCREEN_TOP#2 1024,657 r0 top
C257 "C-0805_C0805_10UF" SILKSCREEN_TOP#2 740,830 r90 top
C258 "C-0402_C0402_1UF" SILKSCREEN_TOP#1 1076,1449.99 r0 top
C259 "C-0402_C0402_100NF" SILKSCREEN_TOP#1 3281,2950.01 r180 top
C260 "C-0402_C0402_1UF" SILKSCREEN_BOTTOM#2 947,2045.01 r0 bottom
C261 "C-1206_C1206_1NF" SILKSCREEN_BOTTOM#7 795,3106 r90 bottom
C290 "C-0402_C0402_100NF" SILKSCREEN_TOP#1 3800.01,3033 r90 top
C291 "C-0402_C0402_100NF" SILKSCREEN_TOP#1 3850.01,3033 r90 top
D1 "DI-TVS-D_SMA_DO-214AC_SMAJ16CA" SILKSCREEN_TOP#5 734,3165 r270 top
D2 "DI-ESD_V0402_PE0402N12G01B" SILKSCREEN_TOP#6 4365,3125 r90 top
D3 "DI-ESD-SE05NRC14GA_DFN2510-10L_" ASSEMBLY_TOP#3 4249,3135 r0 top
D4 "DI-ESD-SE05NRC14GA_DFN2510-10L_" ASSEMBLY_TOP#3 4505,3135 r0 top
D5 "DI-ESD_V0402_PE0402N12G01B" SILKSCREEN_TOP#6 2440,2860 r90 top
D6 "DI-ESD_V0402_PE0402N12G01B" SILKSCREEN_TOP#6 2390,2860 r90 top
D7 "DI-ESD_V0402_PE0402N12G01B" SILKSCREEN_TOP#6 5171,3498 r90 top
D8 "DI-ESD_V0402_PE0402N12G01B" SILKSCREEN_TOP#6 5375,3500 r90 top
D9 "DI-ESD_V0402_PE0402N12G01B" SILKSCREEN_TOP#6 5227,3500 r90 top
D10 "DI-ESD_V0402_PE0402N12G01B" SILKSCREEN_TOP#6 5280,3500 r90 top
D11 "DI-XI-S_SOD123_IC_B5819W-G" SILKSCREEN_BOTTOM#8 4945,2415 r270 bottom
D12 "DI-ESD_V0402_PE0402N12G01B" SILKSCREEN_TOP#6 5330,3500 r90 top
D13 "DI-XI-S_SOD123_IC_B5819W-G" SILKSCREEN_BOTTOM#8 4875,2415 r270 bottom
D14 "DI-ESD-SE05NRC14GA_DFN2510-10L_" SILKSCREEN_TOP#7 3624,3146 r0 top
D15 "DI-ESD_V0402_PE0402N12G01B" SILKSCREEN_TOP#6 4133,3138 r0 top
D16 "DI-ESD_V0402_PE0402N12G01B" SILKSCREEN_TOP#6 3910,3146 r0 top
D17 "DI-ESD-SE05NRC14GA_DFN2510-10L_" SILKSCREEN_TOP#7 3784,3146 r0 top
D18 "DI-ESD_V0402_PE0402N12G01B" SILKSCREEN_TOP#6 5215,905 r90 top
D19 "DI-ESD_V0402_PE0402N12G01B" SILKSCREEN_TOP#6 5113,513 r0 top
D20 "DI-ESD_V0402_PE0402N12G01B" SILKSCREEN_TOP#6 5265,905 r90 top
D21 "DI-ESD_V0402_PE0402N12G01B" SILKSCREEN_TOP#6 4695,585 r270 top
D22 "DI-ESD_V0402_PE0402N12G01B" SILKSCREEN_TOP#6 4795,580 r90 top
D23 "DI-ESD_V0402_PE0402N12G01B" SILKSCREEN_TOP#6 4744,580 r90 top
D24 "DI-ESD_V0402_PE0402N12G01B" SILKSCREEN_TOP#6 4140,705 r180 top
D25 "DI-ESD_V0402_PE0402N12G01B" SILKSCREEN_TOP#6 4325,575 r90 top
D26 "DI-ESD_V0402_PE0402N12G01B" SILKSCREEN_TOP#6 4376,575 r90 top
D27 "DI-ESD_V0402_PE0402N12G01B" SILKSCREEN_TOP#6 5040,3255 r90 top
D28 "DI-ESD_V0402_PE0402N12G01B" SILKSCREEN_TOP#6 4890,3255 r90 top
D29 "DI-ESD_V0402_PE0402N12G01B" SILKSCREEN_TOP#6 5317,2795 r180 top
D30 "DI-ESD_V0402_PE0402N12G01B" SILKSCREEN_TOP#6 5310,2470 r180 top
D31 "DI-ESD_V0402_PE0402N12G01B" SILKSCREEN_TOP#6 5310,2535 r180 top
D32 "DI-ESD_V0402_PE0402N12G01B" SILKSCREEN_TOP#6 5310,2579 r180 top
D33 "DI-ESD_V0402_PE0402N12G01B" SILKSCREEN_TOP#6 5310,2638 r180 top
D34 "DI-ESD-SE05NRC14GA_DFN2510-10L_" SILKSCREEN_TOP#7 3930,745 r180 top
D35 "DI-ESD-SE05NRC14GA_DFN2510-10L_" SILKSCREEN_TOP#7 3490,750 r180 top
D36 "DI-ESD_V0402_PE0402N12G01B" SILKSCREEN_TOP#6 3345,860 r90 top
D37 "DI-ESD-SE05NRC14GA_DFN2510-10L_" SILKSCREEN_TOP#7 3385,750 r180 top
D38 "DI-ESD_V0402_PE0402N12G01B" SILKSCREEN_TOP#6 3295,860 r90 top
D39 "DI-XI-S_SMAF_IC_SM340AF" SILKSCREEN_TOP#8 3845,1105 r0 top
D40 "DI-ESD-SE05NRC14GA_DFN2510-10L_" SILKSCREEN_TOP#7 2654,3345 r0 top
D41 "DI-ESD-SE05NRC14GA_DFN2510-10L_" SILKSCREEN_TOP#7 2772,3345 r0 top
D42 "DI-XI-S_SOD-123F_IC_LMBR140FT1G" SILKSCREEN_TOP#9 3201,3172 r270 top
D43 "DI-XI-S_SOD-123F_IC_LMBR140FT1G" SILKSCREEN_TOP#9 3190,3332 r90 top
D44 "DI-ESD_V0402_PE0402N12G01B" SILKSCREEN_TOP#6 2860,3339 r270 top
D45 "DI-ESD_V0402_PE0402N12G01B" SILKSCREEN_TOP#6 2910,3339 r270 top
D46 "DI-ESD_V0402_PE0402N12G01B" SILKSCREEN_TOP#6 3002,3338 r90 top
D47 "DI-ESD_V0402_PE0402N12G01B" SILKSCREEN_TOP#6 2954,3339 r270 top
D48 "DI-ESD-SE05NRC14GA_DFN2510-10L_" SILKSCREEN_BOTTOM#9 1560,1130 r0 bottom
D49 "DI-ESD-SE05NRC14GA_DFN2510-10L_" SILKSCREEN_TOP#7 1185,1705 r90 top
D50 "DI-XI-S_SMAF_IC_SM340AF" SILKSCREEN_TOP#8 1180,1135 r90 top
D51 "DI-ESD-SE05NRC14GA_DFN2510-10L_" SILKSCREEN_TOP#7 1185,1810 r90 top
D52 "DI-ESD_V0402_PE0402N12G01B" SILKSCREEN_TOP#6 1185,1884 r0 top
D53 "DI-ESD_V0402_PE0402N12G01B" SILKSCREEN_TOP#6 1185,1939 r0 top
D54 "DI-TVS-D_SOD323_SE05D3L01GE" SILKSCREEN_TOP#10 1067,2955 r90 top
D55 "DI-TVS-D_SOD323_SE05D3L01GE" SILKSCREEN_TOP#10 1253,2955 r90 top
D56 "DI-TVS-D_SOD323_SE05D3L01GE" SILKSCREEN_TOP#10 1355,2955 r90 top
D57 "DI-TVS-D_SOD323_SE05D3L01GE" SILKSCREEN_TOP#10 1545,2955 r90 top
D58 "DI-TVS-D_SOD323_SE05D3L01GE" SILKSCREEN_TOP#10 1770,2955 r90 top
D59 "DI-TVS-D_SOD323_SE05D3L01GE" SILKSCREEN_TOP#10 1960,2955 r90 top
D60 "DI-TVS-D_SOD323_SE05D3L01GE" SILKSCREEN_TOP#10 2040,2955 r90 top
D61 "DI-TVS-D_SOD323_SE05D3L01GE" SILKSCREEN_TOP#10 2231,2955 r90 top
D64 "DI-ESD_V0402_PE0402N12G01B" SILKSCREEN_TOP#6 5316,1140 r180 top
D65 "DI-ESD_V0402_PE0402N12G01B" SILKSCREEN_TOP#6 5316,1190 r180 top
D69 "DI-XI-S_SOD523_IC_LRB520S-30T1G" SILKSCREEN_TOP#11 3269,1780 r90 top
D70 "DI-XI-S_SOD523_IC_LRB520S-30T1G" SILKSCREEN_TOP#11 3255,1620 r270 top
D71 "DI-ESD_V0402_ES0402V014CT" SILKSCREEN_TOP#6 5085,3425 r180 top
D72 "DI-ESD_V0402_ES0402V014CT" SILKSCREEN_BOTTOM#10 4625,2570 r270 bottom
D73 "DI-ESD_V0402_ES0402V014CT" SILKSCREEN_BOTTOM#10 4806,2478 r0 bottom
D74 "DI-ESD_V0402_ES0402V014CT" SILKSCREEN_BOTTOM#10 4490,2570 r270 bottom
D75 "DI-ESD_V0402_ES0402V014CT" SILKSCREEN_BOTTOM#10 4757,2570 r270 bottom
D76 "DI-ESD-SE05NRC14GA_DFN2510-10L_" SILKSCREEN_BOTTOM#11 850,2560 r90 bottom
D77 "DI-ESD-SE05NRC14GA_DFN2510-10L_" SILKSCREEN_BOTTOM#11 846,2764 r90 bottom
D79 "DI-ESD_V0402_PE0402N12G01B" SILKSCREEN_BOTTOM#10 870,2949 r90 bottom
D80 "DI-ESD_V0402_PE0402N12G01B" SILKSCREEN_BOTTOM#10 870,2872 r270 bottom
D81 "DI-ESD-SRV05-4_SOT23-6_SRV05-4" SILKSCREEN_TOP#12 1865,2955 r90 top
D82 "DI-ESD-SRV05-4_SOT23-6_SRV05-4" SILKSCREEN_TOP#12 2135,2957 r90 top
D83 "DI-ESD-SRV05-4_SOT23-6_SRV05-4" SILKSCREEN_TOP#12 1160,2960 r90 top
D84 "DI-ESD-SRV05-4_SOT23-6_SRV05-4" SILKSCREEN_TOP#12 1451,2955 r90 top
D90 "DI-XI-S_SOD523_IC_LRB520S-30T1G" SILKSCREEN_TOP#11 5300,1710 r180 top
D96 "DI-ESD_V0402_ES0402V014CT" SILKSCREEN_TOP#6 3296,3101 r90 top
D97 "DI-ESD_V0402_PE0402N12G01B" SILKSCREEN_TOP#6 5225,2795 r0 top
D98 "DI-ESD-SE05NRC14GA_DFN2510-10L_" SILKSCREEN_TOP#7 2660,755 r180 top
D99 "DI-ESD-SE05NRC14GA_DFN2510-10L_" SILKSCREEN_TOP#7 2545,755 r180 top
D100 "DI-ESD_V0402_PE0402N12G01B" SILKSCREEN_TOP#6 2460,755 r90 top
D101 "DI-ESD_V0402_PE0402N12G01B" SILKSCREEN_TOP#6 2410,755 r90 top
D102 "DI-ESD-SE05NRC14GA_DFN2510-10L_" SILKSCREEN_TOP#7 2785,755 r180 top
D103 "DI-ESD-SE05NRC14GA_DFN2510-10L_" SILKSCREEN_TOP#7 2015,730 r180 top
D104 "DI-ESD-SE05NRC14GA_DFN2510-10L_" SILKSCREEN_TOP#7 1885,730 r180 top
D105 "DI-ESD_V0402_PE0402N12G01B" SILKSCREEN_TOP#6 1784,769 r0 top
D106 "DI-ESD_V0402_PE0402N12G01B" SILKSCREEN_TOP#6 1704,769 r180 top
D107 "DI-ESD-SE05NRC14GA_DFN2510-10L_" SILKSCREEN_TOP#7 3427,3146 r0 top
F2 "FUSE-SMD1812_SMD1812_FUSE_16V/2" ASSEMBLY_TOP#4 847,2970 r180 top
H1 "HOLE_4G_MTG170_450_HOLE" SILKSCREEN_TOP#13 5015,655 r0 top
H2 "HOLE_MTG430_620_SMTSO_M3_HOLE" ASSEMBLY_TOP#5 759,2191 r0 top
HOLE1 "MH-NOE_MTG370_600_VIA_MTG370_60" ASSEMBLY_BOTTOM#5 485.85,3219.65 r0 bottom
HOLE2 "MH-NOE_MTG370_600_VIA_MTG370_60" ASSEMBLY_TOP#6 5387.43,636.58 r0 top
HOLE3 "MH-NOE_MTG370_600_VIA_MTG370_60" ASSEMBLY_BOTTOM#5 485.85,636.58 r0 bottom
HOLE4 "MH-NOE_MTG370_600_VIA_MTG370_60" ASSEMBLY_BOTTOM#5 5387.43,3219.65 r0 bottom
J1 "J-DC-044A-2_5_DC-044A-2_0-DIP_D" SILKSCREEN_TOP#14 591.2,3661.65 r270 top
J2 "ATMD097-AED4S-5F_5_DDR4-SODIMM-" SILKSCREEN_TOP#15 2366.23,1759.93 r180 top
J3 "J-TF-01A_TF-01A_SD" SILKSCREEN_TOP#16 4389.96,3522.95 r180 top
J4 "J-A-3P_MX125T-S-3A_MX1.25T-S-3A" SILKSCREEN_TOP#17 2494,3048.87 r180 top
J5 "J-TYPE_C_16P_USB_SMD-TYPE-C-16P" SILKSCREEN_TOP#18 5332.5,3735 r180 top
J6 "J-USB-9AFX2-DIP-W_USB-9AF-DIP_2" SILKSCREEN_TOP#19 3695,3559.33 r180 top
J7 "J-H-4P_PH200-4A_PH2.0-4A" ASSEMBLY_TOP#7 5202.4,387.28 r180 top
J8 "J-H-4P_PH200-4A_PH2.0-4A" ASSEMBLY_TOP#7 4768.7,387.28 r180 top
J9 "J-H-4P_PH200-4A_PH2.0-4A" ASSEMBLY_TOP#7 4335,387.28 r180 top
J10 "J-PJ-326A-3P_PJ-326A-3P_PJ-326" ASSEMBLY_TOP#8 4914.17,3609.02 r270 top
J11 "J-H-2P_PH200-2A_PH2.0-2A" ASSEMBLY_TOP#9 5287.72,2945 r270 top
J12 "J-H-4P_PH200-4A_PH2.0-4A" ASSEMBLY_TOP#7 5512.72,2865 r270 top
J13 "J-FPC-40P_FPC05-40P_FPC05-PUW-4" ASSEMBLY_TOP#10 3571.06,516.85 r0 top
J14 "J-HDMI-19P_HDMI-TYPEA_SMD_HDMI-" ASSEMBLY_TOP#11 2782.17,3659.88 r0 top
J15 "J-FPC-40P_FPC05-40P_FPC05-PUW-4" ASSEMBLY_BOTTOM#6 1143.15,1675 r270 bottom
J16 "J-HDR-D-20_HDR200MRA-2X10_HDR20" ASSEMBLY_TOP#12 530.63,1801.93 r90 top
J17 "J-HDR-6_HDR200MA-1X6_HDR200MA-1" ASSEMBLY_TOP#13 868.15,555 r180 top
J18 "J-H-6P_PH200-6A_PH2.0-6A" ASSEMBLY_TOP#14 835,387.28 r180 top
J19 "J-FPC-24P_FPC05-24P_FPC05-PUW-2" ASSEMBLY_TOP#15 2665,516.85 r0 top
J20 "J-FPC-24P_FPC05-24P_FPC05-PUW-2" ASSEMBLY_TOP#15 1914.29,516.85 r0 top
J21 "RF-IPEX-20279_IPEX-001E_IPEX" ASSEMBLY_TOP#16 5066.63,877 r180 top
J22 "J-RJ45-HR911130C_RJ45-TH_HR9111" ASSEMBLY_TOP#17 1230,3494.84 r0 top
J23 "J-RJ45-HR911130C_RJ45-TH_HR9111" ASSEMBLY_TOP#17 1970,3494.84 r0 top
J24 "J-HDR-D-40_0_HDR254MA-2X18_HDR2" ASSEMBLY_TOP#18 5500,1695 r270 top
J25 "J-A-2P_MX125T-S-2A_MX1.25T-S-2A" SILKSCREEN_TOP#20 1335,479.13 r0 top
J26 "J-MINIPCIE-52P_1_M_MINIPCIE_SOC" SILKSCREEN_TOP#21 4542,1647.35 r0 top
J27 "J-M2_NGFF-M-KEY_1_M2_NGFF-M-KEY" SILKSCREEN_BOTTOM#12 3509.45,1360 r0 bottom
J28 "J-HDR-D-20_HDR200MRA-2X10_HDR20" ASSEMBLY_TOP#12 530.63,2649.33 r90 top
J29 "J-HDR-6_HDR200MA-1X6_HDR200MA-1" ASSEMBLY_TOP#13 610,1076.85 r90 top
J30 "J-H-6P_PH200-6AW_PH2.0-6AW" ASSEMBLY_TOP#19 360.63,1072.64 r90 top
J31 "J-FPC-6P_FPC05-6P_FPC05-FDW-6P" ASSEMBLY_BOTTOM#7 1455,921.85 r0 bottom
J32 "J-H-4P_PH200-4A_PH2.0-4A" ASSEMBLY_TOP#7 593,3611.72 r0 top
L1 "L-CMLP_CMLP-ACM4532_NC/ZCM1812D" ASSEMBLY_TOP#20 725,2760 r270 top
L2 "L-IND_IND_404020_2.2UH/4.3A" ASSEMBLY_TOP#21 2820,2956 r180 top
L3 "L-IND_IND_404020_2.2UH/4.3A" ASSEMBLY_TOP#21 830,1345 r180 top
L4 "L-IND_IND_252012_1UH/3A" ASSEMBLY_TOP#22 1589.5,1255 r0 top
L5 "L-CMLS-ACM2012_CMLS-ACM2012_NC/" SILKSCREEN_TOP#22 5170,3365 r90 top
L6 "L-CMLS-ACM2012_CMLS-ACM2012_NC/" SILKSCREEN_TOP#22 3660,3035 r90 top
L7 "L-CMLS-ACM2012_CMLS-ACM2012_NC/" SILKSCREEN_TOP#22 3587,3033 r90 top
L8 "L-CMLS-ACM2012_CMLS-ACM2012_NC/" SILKSCREEN_TOP#22 5235,1015 r270 top
L9 "L-CMLS-ACM2012_CMLS-ACM2012_NC/" SILKSCREEN_TOP#22 4770,675 r270 top
L10 "L-CMLS-ACM2012_CMLS-ACM2012_NC/" SILKSCREEN_TOP#22 4365,674 r270 top
L11 "FB-0603_L0603_UPZ1608E101-3R0TF" SILKSCREEN_TOP#23 4630,3080 r180 top
L12 "FB-0603_L0603_UPZ1608E101-3R0TF" SILKSCREEN_TOP#23 4630,3135 r180 top
L13 "FB-0603_L0603_UPZ1608E101-3R0TF" SILKSCREEN_TOP#23 5085,3090 r0 top
L14 "FB-0603_L0603_UPZ1608E101-3R0TF" SILKSCREEN_TOP#23 5085,3145 r0 top
L15 "L-IND_IND_252012_4.7UH/1.25A" ASSEMBLY_TOP#22 3670.5,1109 r0 top
L16 "L-CMLS-ACM2012_CMLS-ACM2012_WCM" SILKSCREEN_TOP#22 2624.5,3255 r90 top
L17 "L-CMLS-ACM2012_CMLS-ACM2012_WCM" SILKSCREEN_TOP#22 2683.5,3255 r90 top
L18 "L-CMLS-ACM2012_CMLS-ACM2012_WCM" SILKSCREEN_TOP#22 2742.5,3255 r90 top
L19 "L-CMLS-ACM2012_CMLS-ACM2012_WCM" SILKSCREEN_TOP#22 2802,3255 r90 top
L20 "L-IND_IND_252012_4.7UH/1.25A" ASSEMBLY_TOP#22 1321,1073.5 r270 top
L21 "L-IND_IND_252012_4.7UH/1.25A" ASSEMBLY_TOP#22 4297.5,1333 r180 top
L22 "L-IND_IND_252012_2.2UH/1.9A" ASSEMBLY_TOP#22 1830,1640.5 r270 top
L23 "L-IND_IND_252012_2.2UH/1.9A" ASSEMBLY_TOP#22 2853.5,1610 r0 top
L24 "L-IND_IND_252012_1UH/3A" ASSEMBLY_BOTTOM#8 4380.5,2336 r0 bottom
LED1 "D-LED-DIP-2_LED_P254_2X2DIP_LED" ASSEMBLY_TOP#23 3245,3667.05 r180 top
LED2 "D-LED0603_0_LED0603_GREEN LED06" ASSEMBLY_TOP#24 5168,2223 r270 top
MARK1 "MARK-FID10X20_1_FID1_0X2_3_FID1" PLACE_BOUND_TOP 353,371 r0 top
MARK2 "MARK-FID10X20_1_FID1_0X2_3_FID1" PLACE_BOUND_TOP 5497.66,418.89 r0 top
MARK3 "MARK-FID10X20_0_FID1_0X2_3_FID1" PLACE_BOUND_BOTTOM 1223,3472 r0 bottom
MARK4 "MARK-FID10X20_1_FID1_0X2_3_FID1" ASSEMBLY_TOP#25 875,3600 r0 top
Q1 "N-MOS-Q_SOT523_MMFTN3019E" SILKSCREEN_BOTTOM#13 4835,2190 r90 bottom
Q2 "N-MOS-Q_SOT523_MMFTN3019E" SILKSCREEN_BOTTOM#13 4915,2190 r90 bottom
Q3 "N-MOS-Q_SOT523_MMFTN3019E" SILKSCREEN_TOP#24 3049,3227 r90 top
Q4 "N-MOS-Q_SOT523_MMFTN3019E" SILKSCREEN_TOP#24 3122,3227 r90 top
Q5 "N-MOS-Q_SOT523_MMFTN3019E" SILKSCREEN_TOP#24 2976,3227 r90 top
Q6 "P-MOS_SOT23_CJ3401" SILKSCREEN_TOP#25 1220,670 r180 top
Q7 "N-MOS-Q_SOT523_NC/MMFTN3019E" SILKSCREEN_TOP#24 1595,984 r90 top
Q8 "N-MOS-Q_SOT523_MMFTN3019E" SILKSCREEN_TOP#24 1435,745 r180 top
Q10 "P-MOS_SOT23_CJ3401" SILKSCREEN_TOP#25 5102,1613 r180 top
Q11 "N-MOS-Q_SOT523_NC/MMFTN3019E" SILKSCREEN_TOP#24 875,905 r0 top
Q12 "P-MOS_SOT23_CJ3401" SILKSCREEN_BOTTOM#14 978,2379 r0 bottom
Q13 "N-MOS-Q_SOT523_MMFTN3019E" SILKSCREEN_BOTTOM#13 1135,2259 r270 bottom
Q14 "N-MOS-Q_SOT523_MMFTN3019E" SILKSCREEN_TOP#24 3647,2836 r90 top
Q15 "N-MOS-Q_SOT523_MMFTN3019E" SILKSCREEN_TOP#24 3534,2839 r90 top
Q16 "N-MOS-Q_SOT523_MMFTN3019E" SILKSCREEN_TOP#24 1933,931 r90 top
Q17 "N-MOS-Q_SOT523_MMFTN3019E" SILKSCREEN_TOP#24 2014,931 r90 top
Q19 "N-MOS-Q_SOT523_MMFTN3019E" SILKSCREEN_TOP#24 5305,1605 r0 top
R1 "R-0805_R0805_0R" SILKSCREEN_TOP#26 765,2760 r270 top
R2 "R-0805_R0805_0R" SILKSCREEN_TOP#26 685,2760 r270 top
R3 "R-0402_R0402_100K" SILKSCREEN_TOP#1 3105,2948 r0 top
R4 "R-0402_R0402_105K" SILKSCREEN_TOP#1 3105,3019 r0 top
R5 "R-0402_R0402_47K" SILKSCREEN_TOP#1 3070,2890 r90 top
R6 "R-0402_R0402_20K" SILKSCREEN_TOP#1 3105,3054 r180 top
R7 "R-0402_R0402_47K" SILKSCREEN_TOP#1 3255,3221 r270 top
R8 "R-0402_R0402_1K" SILKSCREEN_TOP#1 3305,3343 r90 top
R9 "R-0402_R0402_15K" SILKSCREEN_TOP#1 3255,3298 r270 top
R10 "R-0402_R0402_1K" SILKSCREEN_TOP#1 3294,3258 r90 top
R11 "R-0402_R0402_105K" SILKSCREEN_TOP#1 1150,1333 r0 top
R12 "R-0402_R0402_20K" SILKSCREEN_TOP#1 1150,1298 r180 top
R13 "R-0402_R0402_1K" SILKSCREEN_TOP#1 1150,1260 r180 top
R14 "R-0402_R0402_1K" SILKSCREEN_TOP#1 1500,1180 r90 top
R15 "R-0402_R0402_45K" SILKSCREEN_TOP#1 1280,1240 r180 top
R16 "R-0402_R0402_10K" SILKSCREEN_TOP#1 1280,1280 r0 top
R17 "R-0805_R0805_0R" SILKSCREEN_BOTTOM#15 1155,2845 r0 bottom
R18 "R-0402_R0402_22R" ASSEMBLY_TOP#2 4194,3047 r90 top
R19 "R-0402_R0402_22R" ASSEMBLY_TOP#2 4234,3047 r90 top
R20 "R-0402_R0402_22R" ASSEMBLY_TOP#2 4271,3047 r90 top
R21 "R-0402_R0402_22R" SILKSCREEN_TOP#1 1585,2289 r270 top
R22 "R-0402_R0402_22R" ASSEMBLY_TOP#2 4478,3044 r90 top
R23 "R-0402_R0402_22R" ASSEMBLY_TOP#2 4515,3044 r90 top
R24 "R-0402_R0402_22R" ASSEMBLY_TOP#2 4550,3044 r90 top
R25 "R-0402_R0402_100R" SILKSCREEN_TOP#1 2485,2855 r90 top
R26 "R-0402_R0402_100R" SILKSCREEN_TOP#1 2345,2855 r90 top
R27 "R-0402_R0402_10K" ASSEMBLY_TOP#2 5125,3498 r270 top
R28 "R-0402_R0402_15K" ASSEMBLY_TOP#2 5088,3498 r270 top
R29 "R-0402_R0402_2.2R" ASSEMBLY_TOP#2 5190,3365 r90 top
R30 "R-0402_R0402_100K" ASSEMBLY_BOTTOM#3 4900,2299 r0 bottom
R31 "R-0402_R0402_NC/0R" ASSEMBLY_BOTTOM#3 4900,2263 r0 bottom
R32 "R-0402_R0402_22R" ASSEMBLY_BOTTOM#2 5130,2195 r90 bottom
R33 "R-0402_R0402_6.8K" ASSEMBLY_BOTTOM#2 5135,2334 r90 bottom
R34 "R-0402_R0402_2.2R" ASSEMBLY_TOP#2 5150,3365 r90 top
R35 "R-0402_R0402_NC/0R" ASSEMBLY_BOTTOM#2 4958,2281 r90 bottom
R36 "R-0402_R0402_510K" ASSEMBLY_BOTTOM#2 5093,2195 r90 bottom
R37 "R-0402_R0402_68K" ASSEMBLY_BOTTOM#2 4915,2580 r90 bottom
R38 "R-0402_R0402_NC/0R" ASSEMBLY_BOTTOM#2 4955,2545 r90 bottom
R39 "R-0402_R0402_33K" ASSEMBLY_BOTTOM#2 4815,2370 r90 bottom
R40 "R-0402_R0402_NC/0R" ASSEMBLY_BOTTOM#2 4874,2545 r90 bottom
R41 "R-0402_R0402_220K" ASSEMBLY_BOTTOM#2 4735,2370 r90 bottom
R42 "R-0402_R0402_2.2R" SILKSCREEN_TOP#1 3679,3035 r90 top
R43 "R-0402_R0402_2.2R" SILKSCREEN_TOP#1 3641,3035 r90 top
R45 "R-0402_R0402_6.8K" ASSEMBLY_TOP#2 4005,3142 r180 top
R46 "R-0402_R0402_2.2R" SILKSCREEN_TOP#1 3604,3035 r90 top
R47 "R-0402_R0402_2.2R" SILKSCREEN_TOP#1 3570,3035 r90 top
R48 "R-0402_R0402_2.2R" SILKSCREEN_TOP#1 3371,3034 r90 top
R49 "R-0402_R0402_2.2R" SILKSCREEN_TOP#1 3408,3034 r90 top
R51 "R-0402_R0402_6.8K" SILKSCREEN_TOP#1 3870,2850 r90 top
R52 "R-0402_R0402_2.2R" SILKSCREEN_TOP#1 5215,1015 r270 top
R53 "R-0402_R0402_0R" ASSEMBLY_TOP#2 4375,2125 r270 top
R54 "R-0402_R0402_10K" ASSEMBLY_TOP#2 4455,1570 r270 top
R55 "R-0402_R0402_10K" ASSEMBLY_TOP#2 4505,1570 r270 top
R56 "R-0402_R0402_2.2R" SILKSCREEN_TOP#1 5255,1015 r270 top
R57 "R-0402_R0402_22R" SILKSCREEN_TOP#1 5165,1180 r270 top
R58 "R-0402_R0402_10K" ASSEMBLY_TOP#2 4360,1570 r270 top
R59 "R-0402_R0402_10K" ASSEMBLY_TOP#2 4229,1694 r0 top
R60 "R-0402_R0402_6.8K" SILKSCREEN_TOP#1 5165,1087 r270 top
R61 "R-0402_R0402_0R" ASSEMBLY_TOP#2 4220,1855 r0 top
R64 "R-0402_R0402_2.2R" SILKSCREEN_TOP#1 4750,675 r270 top
R65 "R-0402_R0402_10K" ASSEMBLY_TOP#2 4215,2020 r0 top
R66 "R-0402_R0402_NC/10K" ASSEMBLY_TOP#2 4335,2125 r90 top
R67 "R-0402_R0402_2.2R" SILKSCREEN_TOP#1 4790,675 r270 top
R68 "R-0402_R0402_1M" ASSEMBLY_TOP#2 4685,1540 r270 top
R69 "R-0402_R0402_0R" ASSEMBLY_TOP#2 4460,2125 r90 top
R70 "R-0402_R0402_22R" SILKSCREEN_TOP#1 4470,715 r0 top
R71 "R-0402_R0402_0R" ASSEMBLY_TOP#2 4495,2125 r90 top
R72 "R-0402_R0402_6.8K" SILKSCREEN_TOP#1 4695,675 r270 top
R73 "R-0402_R0402_2.7K" ASSEMBLY_TOP#2 4575,2125 r90 top
R74 "R-0402_R0402_47K" ASSEMBLY_TOP#2 4215,2077 r180 top
R75 "R-0402_R0402_2.2R" SILKSCREEN_TOP#1 4345,674 r270 top
R76 "R-0402_R0402_0R" ASSEMBLY_TOP#2 4210,1635 r90 top
R77 "R-0402_R0402_22R" SILKSCREEN_TOP#1 4137,1004 r270 top
R78 "R-0402_R0402_2.2R" SILKSCREEN_TOP#1 4385,674 r270 top
R79 "R-0402_R0402_6.8K" SILKSCREEN_TOP#1 4217,675 r90 top
R80 "R-0402_R0402_100R" ASSEMBLY_TOP#2 5307,2684 r0 top
R81 "R-0402_R0402_0R" ASSEMBLY_TOP#2 5080,3255 r270 top
R82 "R-0402_R0402_0R" ASSEMBLY_TOP#2 5000,3255 r90 top
R83 "R-0402_R0402_4.7K" ASSEMBLY_TOP#2 5307,2719 r0 top
R84 "R-0402_R0402_0R" ASSEMBLY_TOP#2 4850,3255 r90 top
R85 "R-0603_R0603_0R" ASSEMBLY_TOP#26 5100,2905 r180 top
R86 "R-0805_R0805_0R" ASSEMBLY_TOP#27 4530,2920 r90 top
R87 "R-0402_R0402_30K" ASSEMBLY_TOP#2 4780,3264 r270 top
R88 "R-0402_R0402_30K" ASSEMBLY_TOP#2 4930,3255 r270 top
R89 "R-0402_R0402_1K" SILKSCREEN_TOP#1 3478,2815 r90 top
R90 "R-0402_R0402_1K" SILKSCREEN_TOP#1 3590,2815 r90 top
R91 "R-0402_R0402_22R" SILKSCREEN_TOP#1 3535,1270 r0 top
R92 "R-0402_R0402_2.2K" SILKSCREEN_TOP#1 3920,915 r90 top
R93 "R-0402_R0402_2.2K" SILKSCREEN_TOP#1 3880,915 r90 top
R94 "R-0402_R0402_22R" SILKSCREEN_TOP#1 3985,835 r270 top
R95 "R-0402_R0402_22R" SILKSCREEN_TOP#1 3950,835 r270 top
R96 "R-0402_R0402_22R" SILKSCREEN_TOP#1 3915,835 r270 top
R97 "R-0402_R0402_22R" SILKSCREEN_TOP#1 3880,835 r270 top
R98 "R-0402_R0402_NC/10K" SILKSCREEN_TOP#1 3232,874 r0 top
R99 "R-0402_R0402_100K" SILKSCREEN_TOP#1 3860,1191 r180 top
R100 "R-0402_R0402_100K" SILKSCREEN_TOP#1 3535,1230 r0 top
R101 "R-0603_R0603_3.9R" SILKSCREEN_TOP#27 4029.52,1220 r270 top
R102 "R-0603_R0603_3.9R" SILKSCREEN_TOP#27 3977,1220 r270 top
R103 "R-0402_R0402_10K" SILKSCREEN_TOP#1 3055,3132 r90 top
R104 "R-0402_R0402_1.8K" SILKSCREEN_TOP#1 3010,3132 r270 top
R105 "R-0402_R0402_10K" SILKSCREEN_TOP#1 3146,3132 r90 top
R106 "R-0402_R0402_1.8K" SILKSCREEN_TOP#1 3094,3132 r90 top
R107 "R-0402_R0402_1K" SILKSCREEN_TOP#1 3083,3338 r270 top
R108 "R-0402_R0402_100K" SILKSCREEN_TOP#1 3044,3339 r270 top
R109 "R-0402_R0402_27K" SILKSCREEN_TOP#1 2969,3132 r270 top
R110 "R-0402_R0402_22R" SILKSCREEN_TOP#1 2269,2189 r270 top
R111 "R-0402_R0402_2.2K" SILKSCREEN_BOTTOM#2 1585,1295 r90 bottom
R112 "R-0402_R0402_2.2K" SILKSCREEN_BOTTOM#2 1624,1295 r90 bottom
R113 "R-0402_R0402_22R" SILKSCREEN_BOTTOM#2 1509,1215 r270 bottom
R114 "R-0402_R0402_22R" SILKSCREEN_BOTTOM#2 1547,1215 r270 bottom
R115 "R-0402_R0402_22R" SILKSCREEN_BOTTOM#2 1585,1215 r270 bottom
R116 "R-0402_R0402_22R" SILKSCREEN_BOTTOM#2 1623,1215 r270 bottom
R117 "R-0402_R0402_100K" SILKSCREEN_TOP#1 1442,940 r0 top
R118 "R-0402_R0402_100K" SILKSCREEN_TOP#1 1564,1134 r180 top
R119 "R-0603_R0603_3.9R" SILKSCREEN_TOP#27 1290,930 r90 top
R120 "R-0603_R0603_3.9R" SILKSCREEN_TOP#27 1343,930 r90 top
R121 "R-0402_R0402_NC/10K" SILKSCREEN_TOP#1 1217,2161 r270 top
R122 "RN_0402X4_RN_0402X4_NC/0R" SILKSCREEN_BOTTOM#16 961,1882 r0 bottom
R123 "RN_0402X4_RN_0402X4_NC/0R" SILKSCREEN_BOTTOM#16 959,1703 r0 bottom
R126 "R-0402_R0402_NC/2.2R" SILKSCREEN_BOTTOM#3 960,1775 r0 bottom
R127 "R-0402_R0402_NC/2.2R" SILKSCREEN_BOTTOM#3 960,1810 r0 bottom
R132 "R-0402_R0402_NC/10K" SILKSCREEN_TOP#1 1710,1033 r270 top
R133 "R-0402_R0402_NC/10K" SILKSCREEN_TOP#1 1690,935 r0 top
R134 "R-0402_R0402_100K" SILKSCREEN_TOP#1 1310,670 r90 top
R135 "R-0402_R0402_0R" SILKSCREEN_TOP#1 1690,975 r180 top
R136 "R-0402_R0402_10K" SILKSCREEN_TOP#1 1409,664 r90 top
R137 "R-0402_R0402_1K" SILKSCREEN_TOP#1 1509,745 r90 top
R138 "R-0402_R0402_0R" SILKSCREEN_TOP#1 1580,814 r180 top
R139 "RN_0402X4_RN_0402X4_0R" SILKSCREEN_TOP#28 2680,871 r270 top
R140 "RN_0402X4_RN_0402X4_0R" SILKSCREEN_TOP#28 2457,864 r270 top
R141 "RN_0402X4_RN_0402X4_NC/0R" SILKSCREEN_BOTTOM#17 2455,865 r270 bottom
R147 "R-0402_R0402_2.2R" SILKSCREEN_TOP#1 2553,870 r270 top
R148 "R-0402_R0402_2.2R" SILKSCREEN_TOP#1 2588,870 r270 top
R149 "R-0402_R0402_22R" SILKSCREEN_TOP#1 3266,2245 r270 top
R150 "R-0402_R0402_22R" SILKSCREEN_TOP#1 2850,870 r270 top
R151 "R-0402_R0402_22R" SILKSCREEN_TOP#1 2885,870 r270 top
R152 "R-0402_R0402_22R" SILKSCREEN_TOP#1 2810,870 r270 top
R153 "R-0402_R0402_22R" SILKSCREEN_TOP#1 2770,870 r270 top
R154 "R-0402_R0402_2.2K" SILKSCREEN_TOP#1 2767,950 r90 top
R155 "R-0402_R0402_2.2K" SILKSCREEN_TOP#1 2821,950 r90 top
R156 "R-0402_R0402_10K" SILKSCREEN_TOP#1 2960,870 r90 top
R157 "R-0402_R0402_2.2R" SILKSCREEN_TOP#1 1726,830 r270 top
R158 "R-0402_R0402_2.2R" SILKSCREEN_TOP#1 1763,830 r270 top
R159 "R-0402_R0402_NC/22R" SILKSCREEN_TOP#1 2062,818 r270 top
R160 "R-0402_R0402_NC/22R" SILKSCREEN_TOP#1 2023,818 r270 top
R161 "R-0402_R0402_10K" SILKSCREEN_TOP#1 1985,818 r90 top
R162 "R-0402_R0402_10K" SILKSCREEN_TOP#1 2103,899 r0 top
R163 "R-0402_R0402_100R" SILKSCREEN_TOP#1 2630,2270 r270 top
R164 "R-0402_R0402_22R" SILKSCREEN_TOP#1 2180,900 r180 top
R165 "R-0402_R0402_22R" SILKSCREEN_TOP#1 2280,900 r180 top
R166 "R-0402_R0402_10K" SILKSCREEN_TOP#1 2140,818 r90 top
R172 "R-0402_R0402_24.9K" SILKSCREEN_TOP#1 2490,1090 r270 top
R173 "R-0402_R0402_20K" SILKSCREEN_TOP#1 2450,1090 r90 top
R175 "R-0402_R0402_17.4K" SILKSCREEN_TOP#1 2690,1090 r270 top
R176 "R-0402_R0402_20K" SILKSCREEN_TOP#1 2650,1090 r90 top
R177 "R-0402_R0402_49.9K" SILKSCREEN_TOP#1 2941,1087 r270 top
R179 "R-0402_R0402_20K" SILKSCREEN_TOP#1 2895,1087 r90 top
R180 "R-0402_R0402_NC/10K" SILKSCREEN_TOP#1 4417,1407 r180 top
R181 "R-0402_R0402_22R" SILKSCREEN_TOP#1 4455,1350 r270 top
R182 "R-0402_R0402_22R" SILKSCREEN_TOP#1 4415,1350 r270 top
R183 "R-0402_R0402_22R" SILKSCREEN_TOP#1 4607,1350 r270 top
R184 "R-0402_R0402_22R" SILKSCREEN_TOP#1 4570,1350 r270 top
R185 "R-0402_R0402_NC/10K" SILKSCREEN_TOP#1 4532,1425 r270 top
R186 "R-0402_R0402_22R" SILKSCREEN_TOP#1 4530,1350 r270 top
R187 "R-0402_R0402_22R" SILKSCREEN_BOTTOM#2 3424,2591 r270 bottom
R191 "R-0402_R0402_NC/0R" SILKSCREEN_TOP#1 4795,1235 r270 top
R196 "R-0402_R0402_0R" SILKSCREEN_TOP#1 4656,1350 r270 top
R199 "R-0402_R0402_22R" SILKSCREEN_TOP#1 4825,1020 r180 top
R200 "R-0402_R0402_0R" SILKSCREEN_TOP#1 4120,1315 r270 top
R201 "R-0402_R0402_NC/10K" SILKSCREEN_TOP#1 4585,715 r0 top
R202 "R-0805_R0805_NC/0R" ASSEMBLY_TOP#27 5135,1715 r180 top
R203 "R-0402_R0402_100K" ASSEMBLY_TOP#2 5190,1635 r90 top
R204 "R-0402_R0402_10K" SILKSCREEN_TOP#1 4175,1140 r0 top
R205 "R-0402_R0402_0R" SILKSCREEN_TOP#1 4175,1060 r0 top
R206 "R-0402_R0402_NC/0R" SILKSCREEN_TOP#1 4175,1100 r0 top
R207 "R-0402_R0402_10K" ASSEMBLY_TOP#2 5230,1635 r90 top
R208 "R-0402_R0402_NC/0R" SILKSCREEN_TOP#1 4195,1004 r270 top
R209 "R-0402_R0402_0R" SILKSCREEN_TOP#1 4256,675 r90 top
R210 "R-0402_R0402_NC/0R" SILKSCREEN_TOP#1 4292,675 r90 top
R211 "R-0402_R0402_510R" SILKSCREEN_TOP#1 1910,2050 r180 top
R213 "R-0402_R0402_510R" SILKSCREEN_TOP#1 1645,2960 r270 top
R214 "R-0402_R0402_2.2R" SILKSCREEN_TOP#1 1485,2055 r90 top
R215 "R-0402_R0402_2.2R" SILKSCREEN_TOP#1 1525,2055 r90 top
R216 "R-0402_R0402_100R" SILKSCREEN_TOP#1 1960,1855 r180 top
R219 "R-0402_R0402_120R" SILKSCREEN_TOP#1 2045,1855 r180 top
R220 "R-0402_R0402_2.2R" SILKSCREEN_TOP#1 1665,2055 r90 top
R221 "R-0402_R0402_2.2R" SILKSCREEN_TOP#1 1702,2055 r90 top
R222 "R-0402_R0402_2.2R" SILKSCREEN_TOP#1 1775,2055 r90 top
R223 "R-0402_R0402_2.2R" SILKSCREEN_TOP#1 1812,2055 r90 top
R224 "R-0402_R0402_22R" SILKSCREEN_TOP#1 1505,2270 r270 top
R225 "R-0402_R0402_NC/4.7K" SILKSCREEN_TOP#1 1855,1788 r180 top
R226 "R-0402_R0402_4.7K" SILKSCREEN_TOP#1 1855,1750 r0 top
R227 "R-0402_R0402_22R" SILKSCREEN_TOP#1 1465,2270 r270 top
R228 "R-0402_R0402_22R" SILKSCREEN_TOP#1 1431,2809 r90 top
R229 "R-0402_R0402_NC/4.7K" SILKSCREEN_TOP#1 1855,1843 r180 top
R230 "R-0402_R0402_4.7K" SILKSCREEN_TOP#1 2045,1750 r270 top
R231 "R-0402_R0402_22R" SILKSCREEN_TOP#1 1395,2809 r90 top
R232 "R-0402_R0402_22R" SILKSCREEN_TOP#1 1425,2270 r270 top
R233 "R-0402_R0402_4.7K" SILKSCREEN_TOP#1 1960,1735 r180 top
R234 "R-0402_R0402_22R" SILKSCREEN_TOP#1 1325,2809 r90 top
R235 "R-0402_R0402_4.7K" SILKSCREEN_TOP#1 1595,1665 r90 top
R236 "R-0402_R0402_4.7K" SILKSCREEN_TOP#1 1436,1485 r270 top
R237 "R-0402_R0402_4.7K" SILKSCREEN_TOP#1 1632,1665 r90 top
R238 "R-0402_R0402_NC/4.7K" SILKSCREEN_TOP#1 1595,1485 r270 top
R239 "R-0402_R0402_4.7K" SILKSCREEN_TOP#1 1555,1665 r90 top
R240 "R-0402_R0402_NC/4.7K" SILKSCREEN_TOP#1 1555,1485 r270 top
R241 "R-0402_R0402_2.49K" SILKSCREEN_TOP#1 1855,1955 r180 top
R242 "R-0402_R0402_4.7K" SILKSCREEN_TOP#1 1516,1665 r90 top
R243 "R-0402_R0402_NC/4.7K" SILKSCREEN_TOP#1 1515,1485 r270 top
R245 "R-0402_R0402_NC/4.7K" SILKSCREEN_TOP#1 1478,1665 r90 top
R246 "R-0402_R0402_4.7K" SILKSCREEN_TOP#1 1475,1485 r270 top
R248 "R-0402_R0402_0R" SILKSCREEN_TOP#1 1379,1926 r0 top
R249 "R-0402_R0402_1.8K" SILKSCREEN_TOP#1 1460,1897 r0 top
R250 "R-0402_R0402_0R" SILKSCREEN_TOP#1 1705,1470 r180 top
R252 "R-0402_R0402_22R" SILKSCREEN_TOP#1 1555,1575 r270 top
R253 "R-0402_R0402_22R" SILKSCREEN_TOP#1 1515,1575 r270 top
R254 "R-0402_R0402_22R" SILKSCREEN_TOP#1 1475,1575 r270 top
R255 "R-0402_R0402_22R" SILKSCREEN_TOP#1 1435,1575 r270 top
R256 "R-0402_R0402_22R" SILKSCREEN_TOP#1 1635,1575 r270 top
R257 "R-0402_R0402_22R" SILKSCREEN_TOP#1 1595,1575 r270 top
R258 "R-0402_R0402_0R" SILKSCREEN_TOP#1 1380,2035 r0 top
R259 "R-0402_R0402_2.2R" SILKSCREEN_TOP#1 2499,2055 r90 top
R260 "R-0402_R0402_2.2R" SILKSCREEN_TOP#1 2533,2055 r90 top
R261 "R-0402_R0402_2.2R" SILKSCREEN_TOP#1 2600,2055 r90 top
R262 "R-0402_R0402_2.2R" SILKSCREEN_TOP#1 2635,2055 r90 top
R263 "R-0402_R0402_2.2R" SILKSCREEN_TOP#1 2670,2055 r90 top
R264 "R-0402_R0402_2.2R" SILKSCREEN_TOP#1 2710,2055 r90 top
R265 "R-0402_R0402_2.2R" SILKSCREEN_TOP#1 2780,2055 r90 top
R266 "R-0402_R0402_2.2R" SILKSCREEN_TOP#1 2817,2055 r90 top
R267 "R-0402_R0402_510R" SILKSCREEN_TOP#1 1680,2960 r90 top
R268 "R-0402_R0402_510R" SILKSCREEN_TOP#1 2359,3265 r270 top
